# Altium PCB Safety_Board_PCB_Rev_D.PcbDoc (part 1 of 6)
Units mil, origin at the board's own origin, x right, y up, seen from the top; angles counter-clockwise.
Board outline 11000 x 4400 mil, 6 copper layers (L1-TOP, L2-Plane, L3-Signal, L4-Signal, L5-Plane, L6-BOT); 712 components, 540 nets, 2214 pads, 875 vias.
Unrouted connection lines stored in the file: 3.
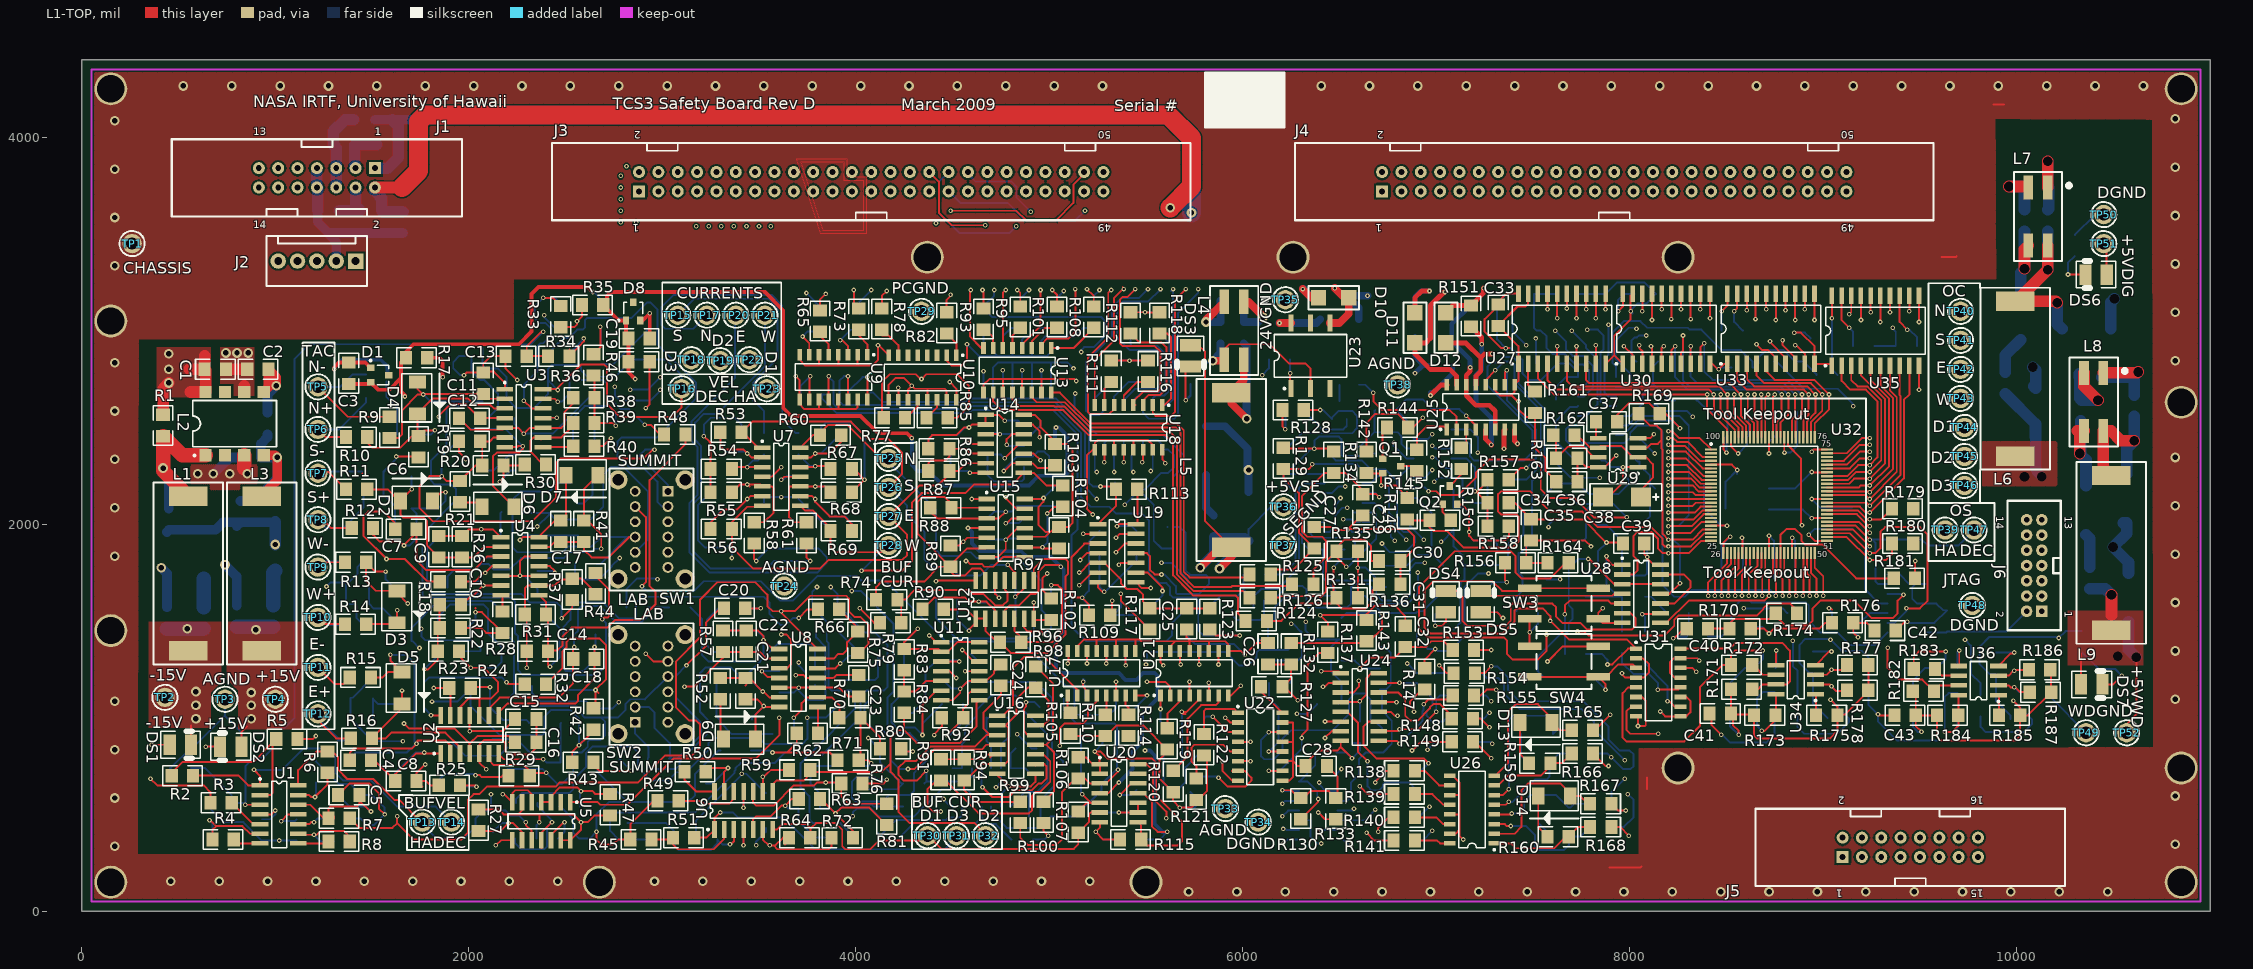
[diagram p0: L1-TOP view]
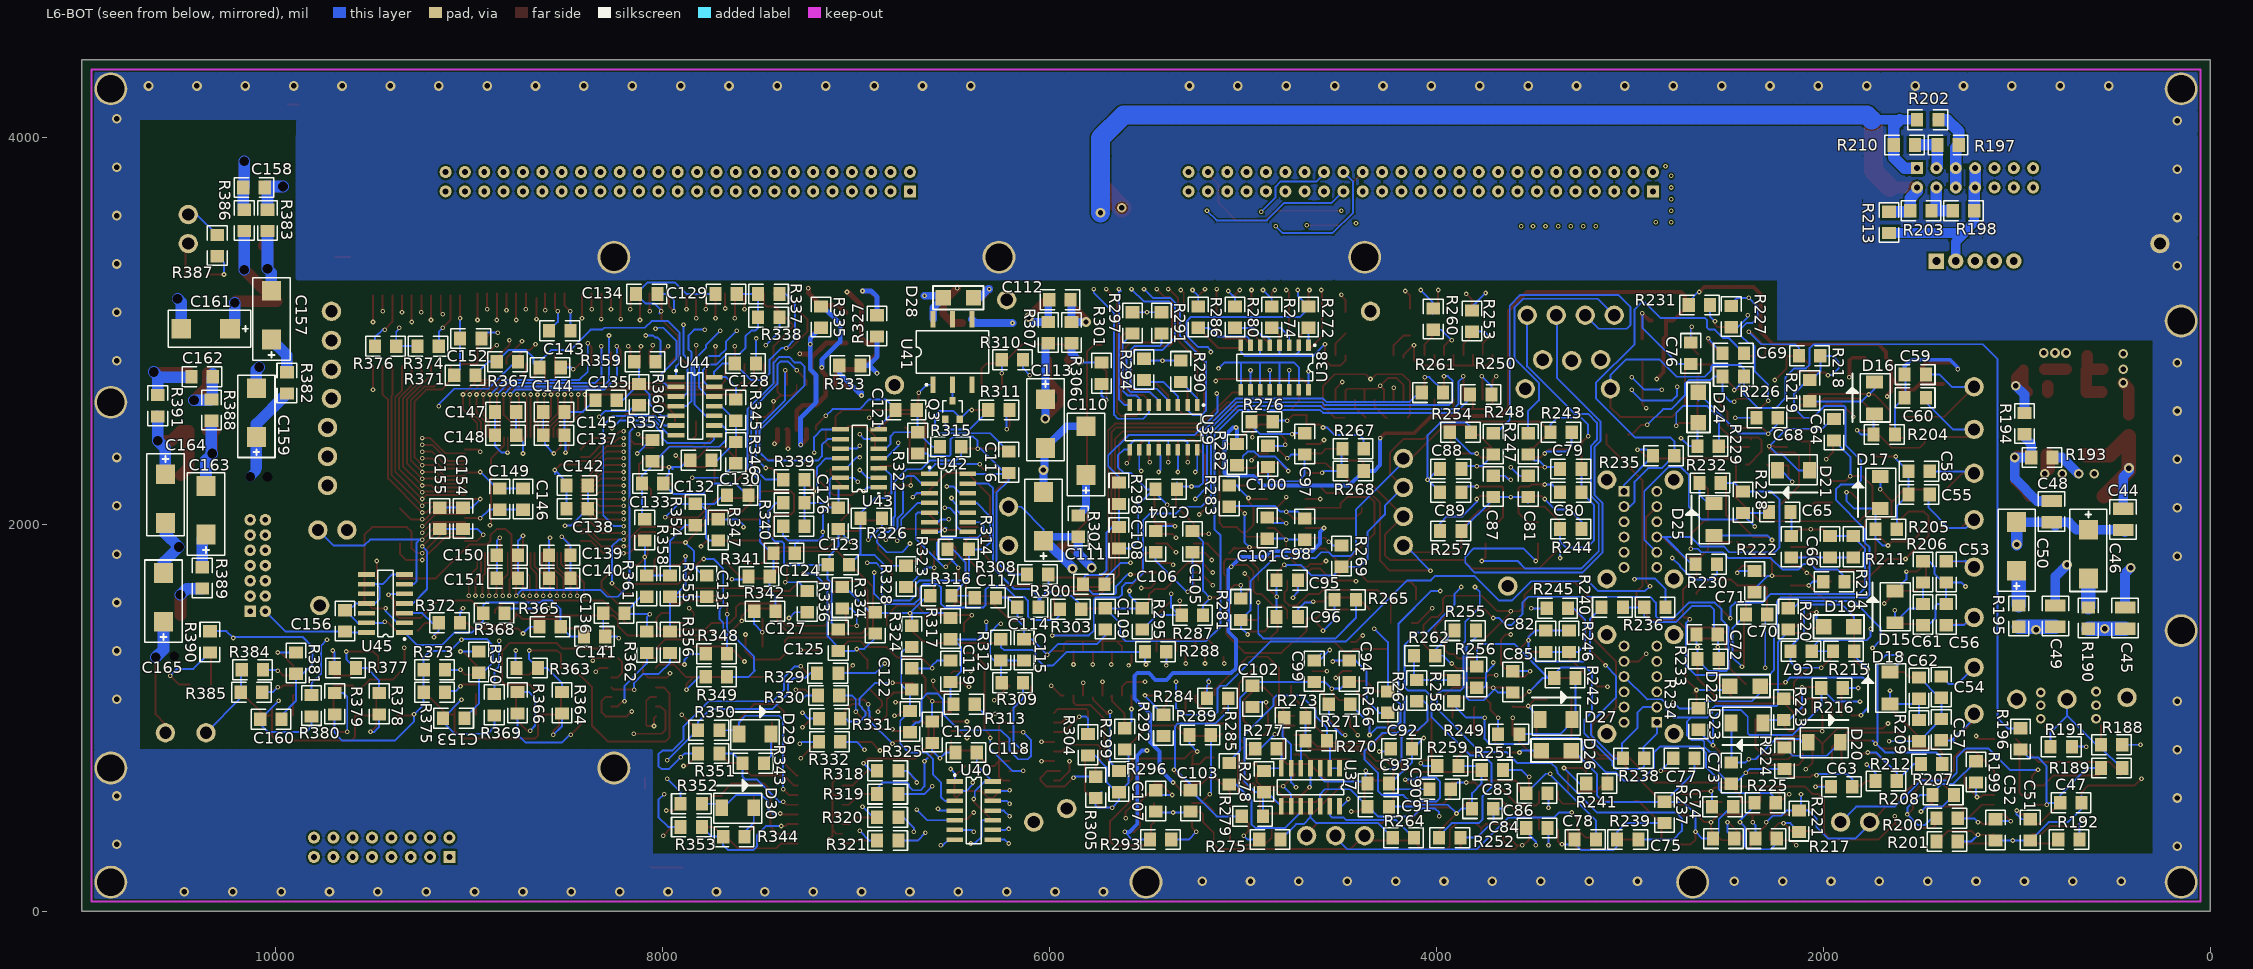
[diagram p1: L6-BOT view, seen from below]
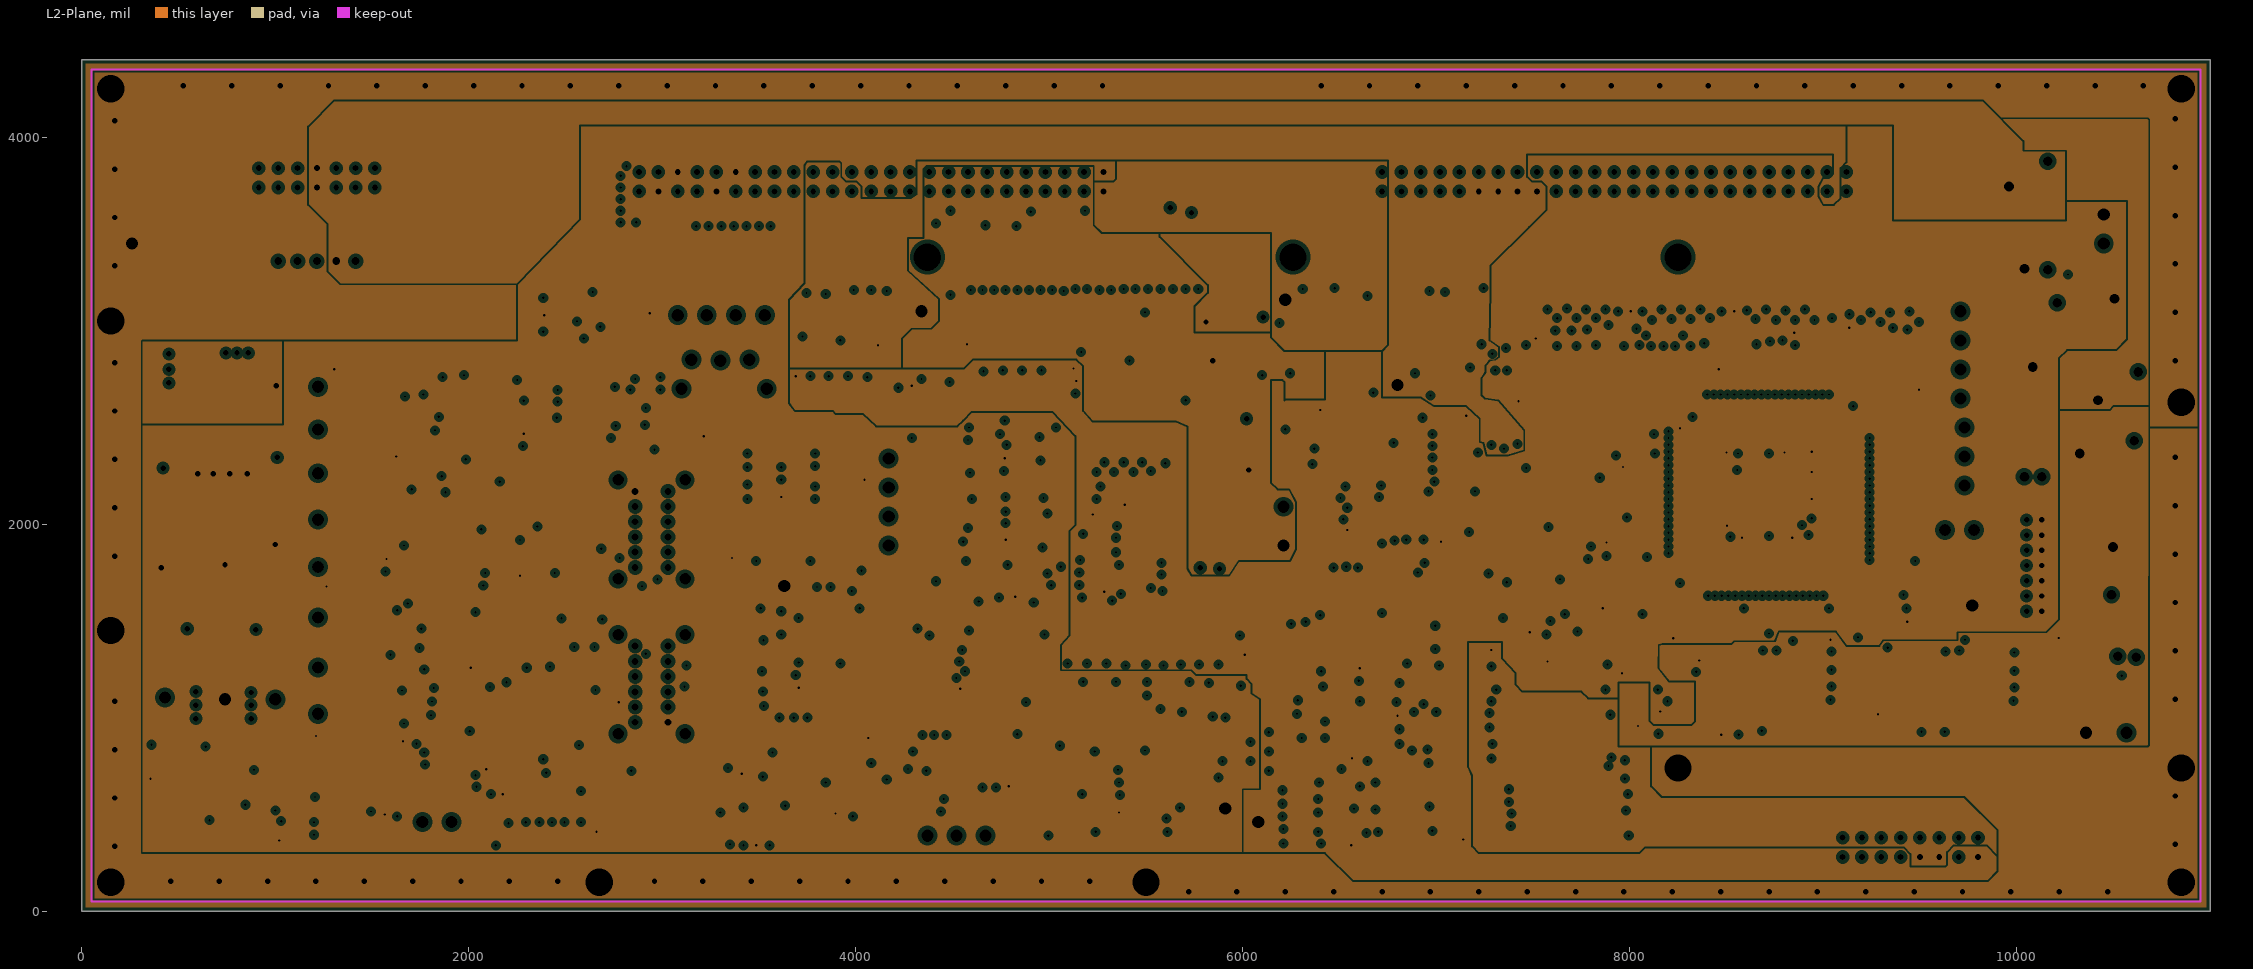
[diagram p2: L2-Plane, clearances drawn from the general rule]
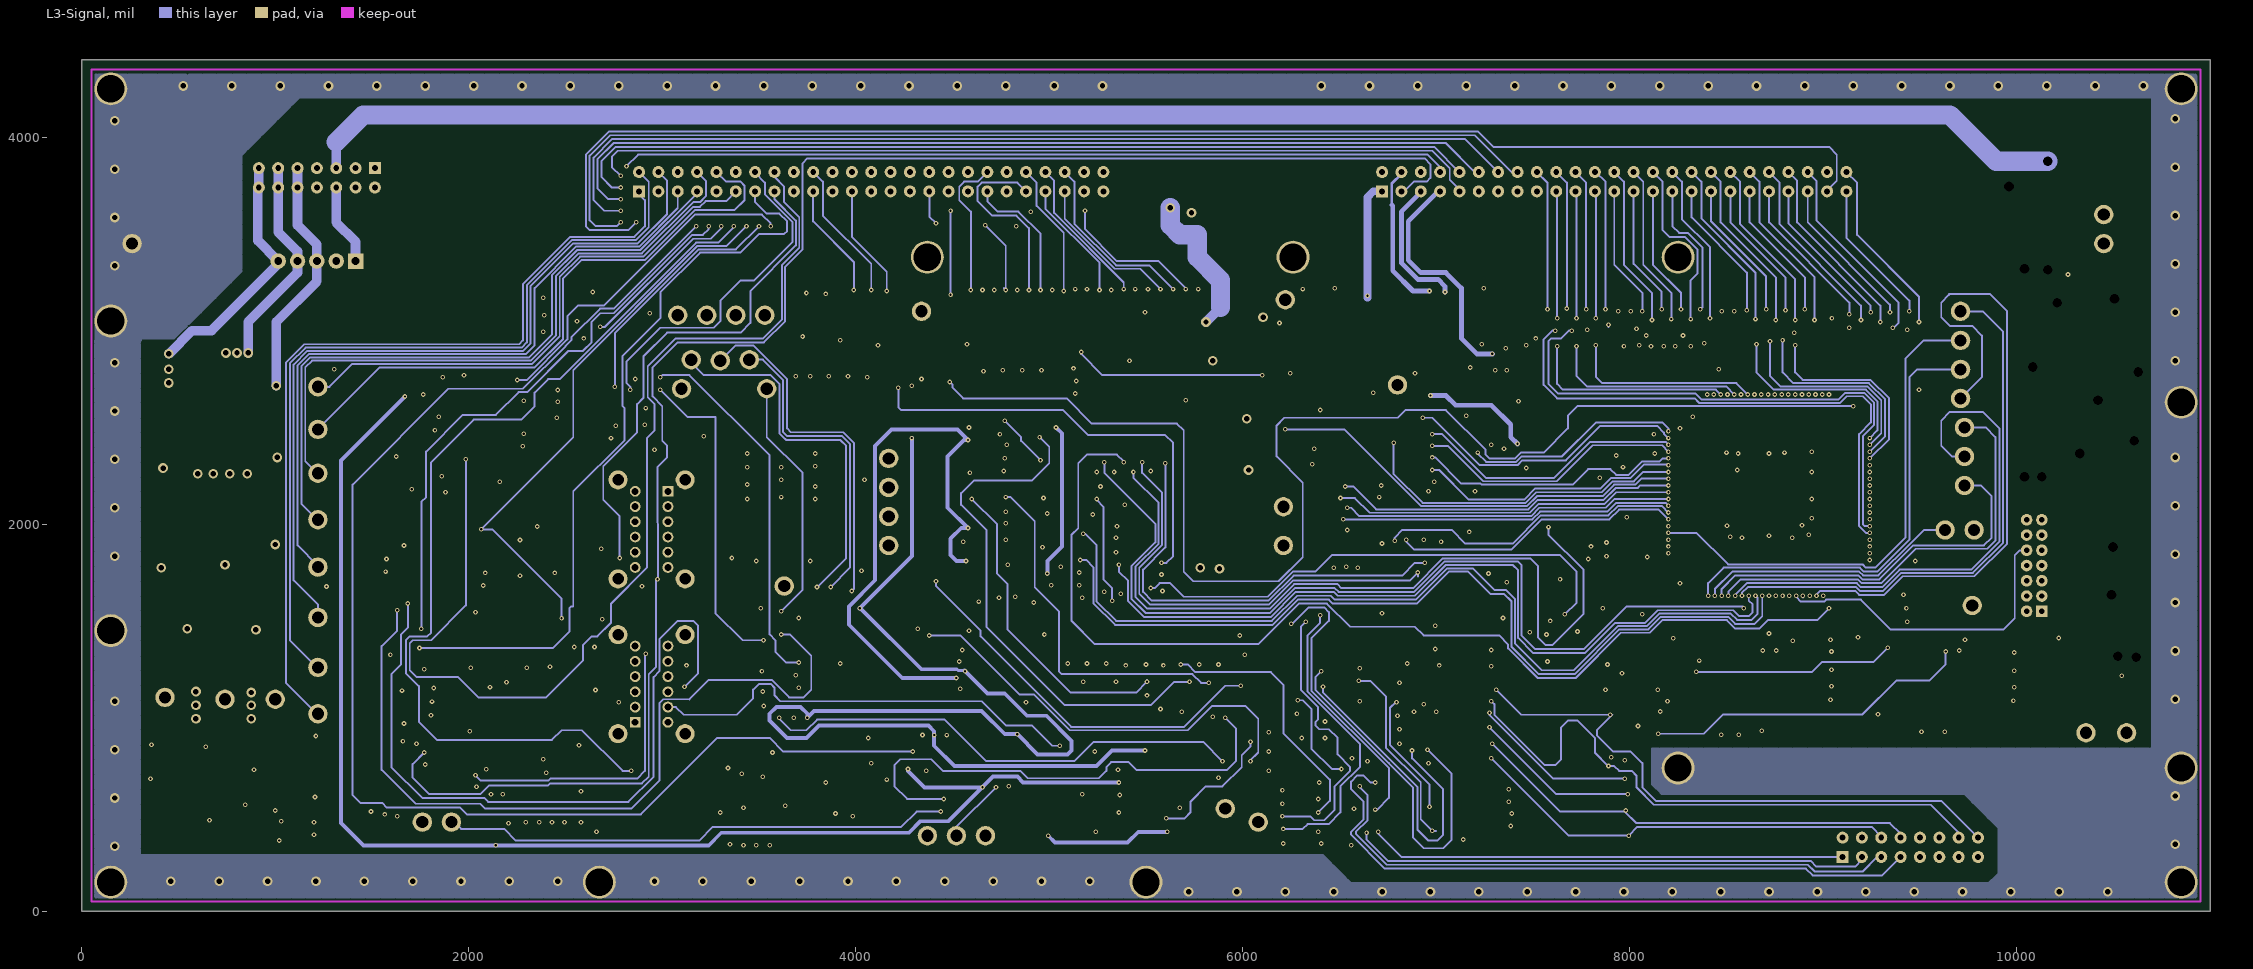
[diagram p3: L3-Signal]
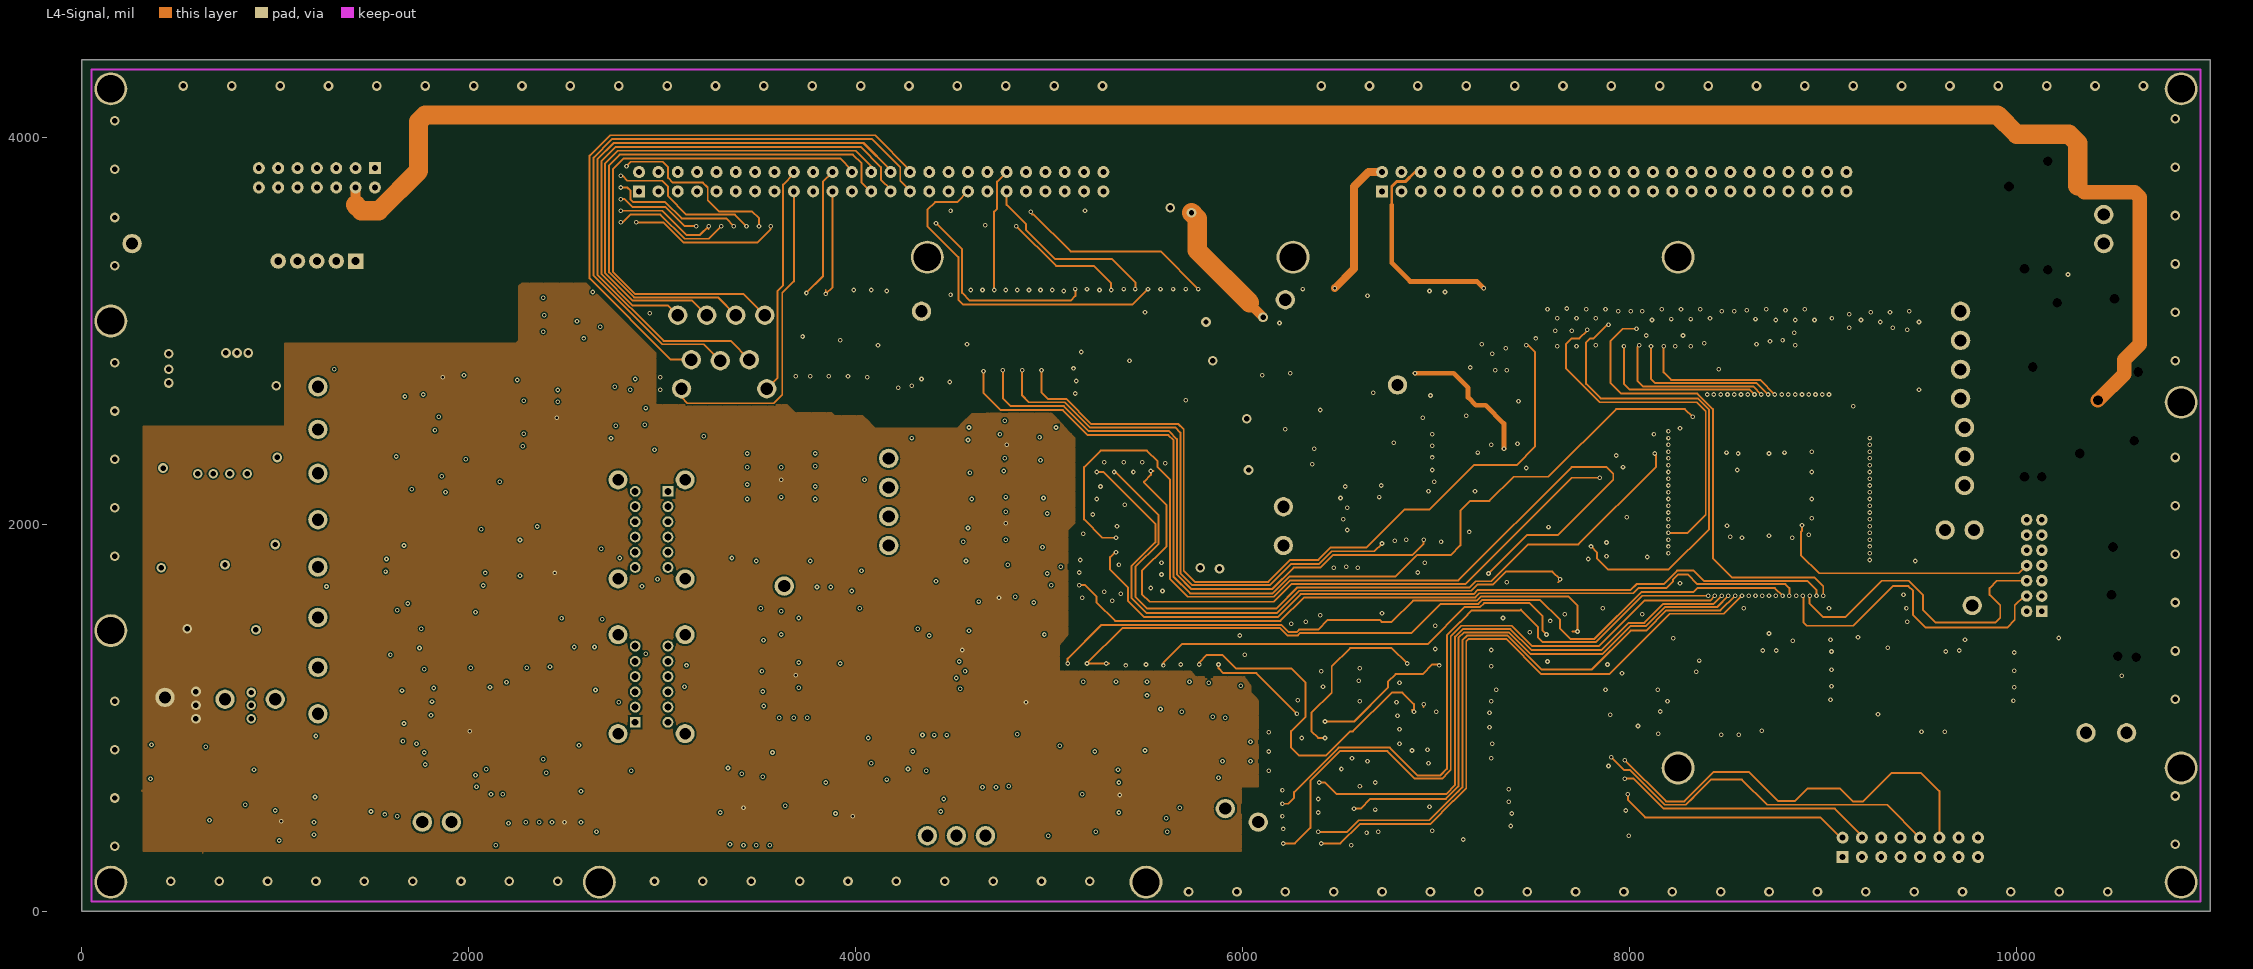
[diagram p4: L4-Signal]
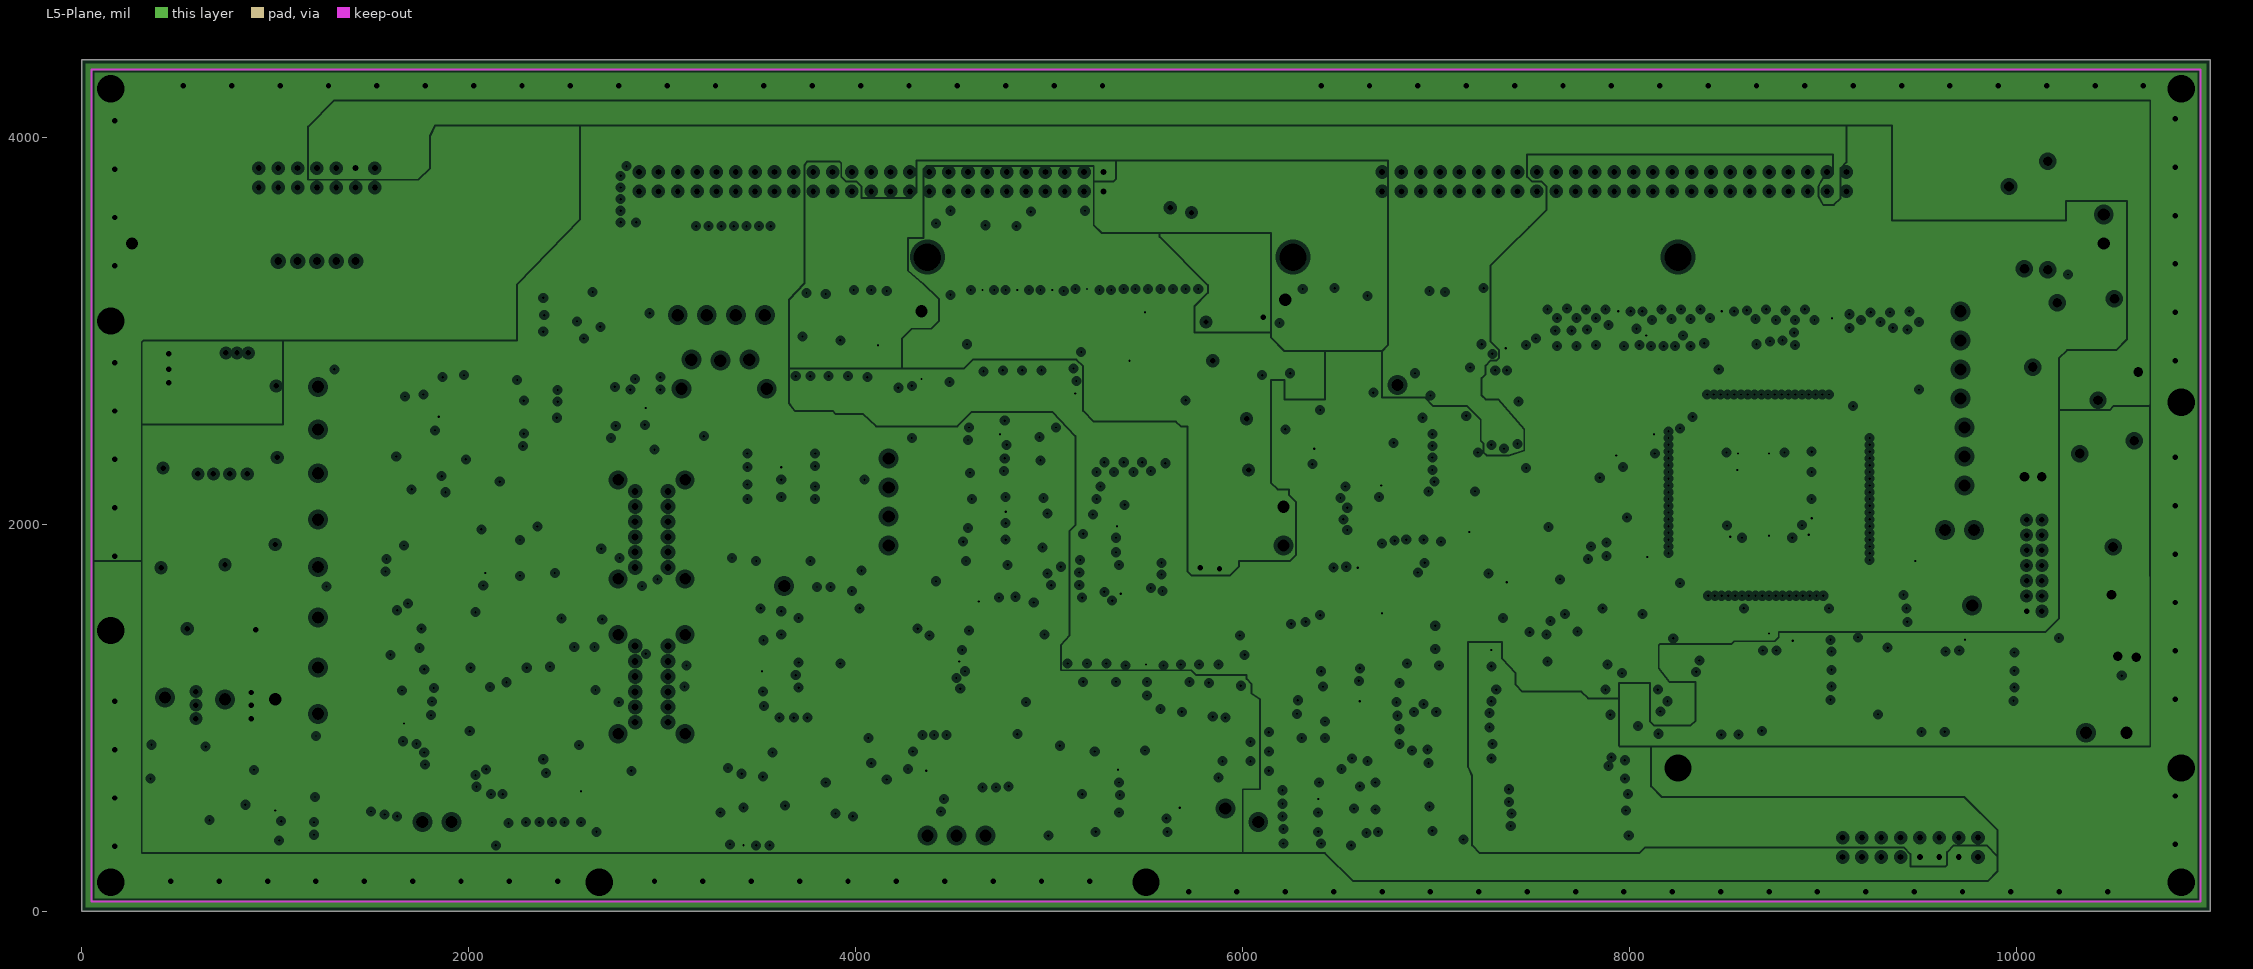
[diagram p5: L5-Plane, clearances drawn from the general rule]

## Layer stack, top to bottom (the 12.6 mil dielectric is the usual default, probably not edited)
L1-TOP: signal copper 1.4
Dielectric: core 12.6, FR-4, Dk 4.8
L2-Plane: plane copper 1.4, net (Multiple Nets)
Dielectric: prepreg 12.6, FR-4, Dk 4.8
L3-Signal: signal copper 1.4
Dielectric: core 12.6, FR-4, Dk 4.8
L4-Signal: signal copper 1.4
Dielectric: prepreg 12.6, FR-4, Dk 4.8
L5-Plane: plane copper 1.4, net (Multiple Nets)
Dielectric: core 12.6, FR-4, Dk 4.8
L6-BOT: signal copper 1.4

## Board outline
0,0 11000,0 11000,4400 0,4400 0,0

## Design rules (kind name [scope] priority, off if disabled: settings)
Clearance Clearance_1 [InPolygon vs IsPad] p1: gap=10
Clearance [All] p2: gap=7
ComponentClearance ComponentClearance_1 [All] p1: gap=2 collisioncheckmode=1
FanoutControl Fanout_BGA_1 [IsBGA] p1: bgadir=Out bgaviamode=Centered fanoutstyle=Auto fanoutdirection=Alternating viagrid=1 // Fanout_BGA (Default Rule)
FanoutControl Fanout_LCC_1 [IsLCC] p2: bgadir=Out bgaviamode=Centered fanoutstyle=Auto fanoutdirection=Alternating viagrid=1 // Fanout_LCC (Default Rule)
FanoutControl Fanout_SOIC_1 [IsSOIC] p3: bgadir=Out bgaviamode=Centered fanoutstyle=Auto fanoutdirection=Alternating viagrid=1 // Fanout_SOIC (Default Rule)
FanoutControl Fanout_Small_1 [(CompPinCount < 5)] p4: bgadir=Out bgaviamode=Centered fanoutstyle=Auto fanoutdirection=OutThenIn viagrid=1 // Fanout_Small (Default Rule)
FanoutControl Fanout_Default_1 [All] p5: bgadir=Out bgaviamode=Centered fanoutstyle=Auto fanoutdirection=Alternating viagrid=1 // Fanout_Default (Default Rule)
Height Height_1 [All] p1: minheight=0 maxheight=1000 prefheight=500
HoleSize HoleSize_1 [All] p1: absolutevalues=TRUE maxlimit=200 minlimit=1 maxpercent=80.000 minpercent=20.000
LayerPairs LayerPairs_1 [All] p1: enforce=TRUE
MatchedLengths "Encoder HA" [InNetClass('Encoder HA Nets')] p1: tolerance=100 amplitude=200 gap=20 style=90-Degree
MatchedLengths "Encoder DEC" [InNetClass('Encoder DEC Nets')] p2: tolerance=100 amplitude=200 gap=20 style=90-Degree
MatchedLengths JTAG [InNetClass('JTAG Nets')] p3: tolerance=50 amplitude=200 gap=20 style=90-Degree
PasteMaskExpansion PasteMaskExpansion_1 [All] p1: expansion=0
PlaneClearance PlaneClearance_1 [All] p1: clearance=20
PlaneConnect [All] p1: planeconnectstyle=Relief reliefexpansion=20 reliefentries=4 reliefconductorwidth=10 reliefairgap=10
PolygonConnect PolygonConnect_1 [All] p1: connectstyle=Direct reliefconductorwidth=10 reliefentries=4 polygonreliefangle="90 Angle"
RoutingLayers [All] p1: top layer=Horizontal mid layer 3="Not Used" mid layer 4="Not Used" bottom layer=Vertical
RoutingPriority RoutingPriority_1 [All] p1: routingpriority=0
RoutingTopology RoutingTopology_1 [All] p1: topology=Shortest
RoutingVias [All] p1: holewidth=28 width=50 viastyle="Through Hole" minholewidth=28 minwidth=50 maxholewidth=28 maxwidth=50
ShortCircuit ShortCircuit_1 [All] p1: allowed=FALSE
SolderMaskExpansion SolderMaskExpansion_1 [All] p1: expansion=4
TestPointUsage TestPointUsage_1 [All] p1: valid=0 allowmultiple=FALSE
Testpoint Testpoint_1 [All] p1: side=15 testpointundercomponent=TRUE minsize=40 maxsize=100 preferedsize=60 minholesize=0 maxholesize=40 preferedholesize=32 testpointgrid=1 style=1023 order=-539222988
UnRoutedNet UnRoutedNet_1 [All] p1:
Width [All] p1: maxlimit=250 minlimit=7 preferedwidth=10 toplayer_prefwidth=20 minimp=50.000000 maximp=50.000000 favimp=50.000000
1 further rules are at their usual default settings.

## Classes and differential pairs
component class Sheet_Symbol_WD: C39 C41 C43 C131 C136 C153 C160 DS4 DS5 R171 R172 R173 R175 R177 R178 R182 R183 R184 R185 R186 R187 R334 R336 R348 R349 R355 R356 R361 R362 R363 R364 R366 R369 R370 R373 R375 R377 R378 R379 R380 R381 R384 R385 SW3 SW4 U28 U31 U34 U36
component class Sheet_Symbol_Power_Filter: C1 C2 C3 C19 C44 C45 C46 C48 C49 C50 C110 C111 C112 C113 C157 C158 C159 C161 C162 C163 C164 C165 D1 D8 DS1 DS2 DS3 DS6 DS7 L1 L2 L3 L4 L5 L6 L7 L8 L9 R1 R17 R46 R188 R190 R191 R193 R194 R195 R197 R198 R202 R203 R210 R213 R301 R302 R306 R307 R382 R383 R386 R387 R388 R389 R390 R391 TP1 TP2 TP3 TP4 TP24 TP29 TP33 TP34 TP36 TP37 TP38 TP48 TP49 TP50 TP51 TP52
component class SB_PG1: J1 J2 J3 J4 J5
component class Sheet_Symbol_CPLD: C33 C36 C37 C38 C134 C137 C138 C139 C140 C142 C143 C145 C146 C147 C148 C149 C150 C151 C152 C154 C155 J6 R161 R162 R163 R169 R179 R180 R181 R374 R376 U27 U29 U30 U32 U33 U35
component class Sheet_Symbol_Dec_Tach: C6 C7 C9 C10 C11 C12 C13 C14 C17 C55 C58 C59 C60 C64 C65 C66 C67 C68 C69 C70 C71 C76 D2 D4 D6 D7 D16 D17 D19 D21 D24 D25 R9 R10 R11 R12 R18 R19 R20 R21 R22 R23 R26 R28 R30 R31 R33 R34 R35 R36 R37 R38 R39 R40 R41 R44 R48 R110 R204 R205 R211 R214 R215 R218 R219 R222 R226 R227 R228 R229 R230 R231 R232 R235 SW1 TP5 TP6 TP7 TP8 TP16 U3 U4
component class Sheet_Symbol_Encoder: C120 D13 D14 D29 D30 R138 R139 R140 R141 R148 R149 R153 R154 R155 R159 R160 R165 R166 R167 R168 R318 R319 R320 R321 R329 R330 R331 R332 R343 R344 R350 R351 R352 R353 U24 U26
component class Sheet_Symbol_HA_Tach: C4 C8 C15 C16 C18 C20 C21 C22 C23 C53 C54 C56 C57 C61 C62 C63 C72 C73 C77 C82 C85 C92 D3 D5 D9 D15 D18 D20 D22 D23 D26 D27 R13 R14 R15 R16 R24 R25 R29 R32 R42 R43 R52 R57 R62 R66 R70 R71 R75 R80 R206 R207 R209 R212 R216 R220 R223 R224 R233 R234 R236 R238 R240 R242 R245 R246 R249 R255 R256 R258 R259 R262 R263 R284 SW2 TP9 TP10 TP11 TP12 TP23 U2 U8
component class Sheet_Symbol_Input_Buffer: C25 C104 C105 C106 C108 C109 C121 C124 C128 C129 C135 C144 R65 R73 R78 R82 R109 R113 R117 R123 R250 R253 R260 R261 R272 R274 R280 R286 R287 R295 R298 R300 R315 R322 R323 R326 R337 R338 R359 R360 R367 R371 U9 U10 U19 U38 U44
component class Sheet_Symbol_Overcurrent: C35 C79 C81 C87 C88 C95 C96 C98 C101 C119 R53 R54 R60 R67 R74 R79 R88 R89 R90 R96 R102 R120 R156 R164 R243 R247 R248 R254 R265 R269 R281 R299 R313 R317 TP15 TP17 TP25 TP26 TP40 TP41 U7 U12 U15 U21
component class Sheet_Symbol_Overspeed: C5 C24 C32 C40 C47 C51 C52 C102 R2 R5 R6 R7 R27 R47 R91 R94 R98 R99 R100 R105 R137 R143 R170 R174 R189 R196 R199 R208 R217 R221 R225 R305 TP13 TP14 TP39 TP47 U1 U16 U17
component class Sheet_Symbol_Relays: C34 C126 D10 D11 D12 D28 Q1 Q2 Q3 R128 R142 R144 R145 R146 R150 R151 R152 R157 R158 R310 R311 R327 R333 R335 R339 R340 TP35 U23 U25 U41
component class Sheet_Symbol_Spares: C74 C75 R3 R4 R8 R49 R50 R77 R85 R114 R192 R200 R201 R241 R264 R275 R285 R288 R292 U5

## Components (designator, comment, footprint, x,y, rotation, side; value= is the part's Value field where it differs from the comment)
C1 "1uF" 1206 690,2800 r0 top
C2 "1uF" 1206 910,2800 r0 top
C3 "1uF" 1206 1380,2780 r270 top
C4 "0.022uF" 1206 1440,780 r180 top
C5 "1uF" 1206 1380,600 r0 top
C6 "0.022uF" 1206 1740,2400 r90 top
C7 "0.022uF" 1206 1674.65,1973.11 r0 top
C8 "0.068uF" 1206 1674.65,673.11 r0 top
C9 "0.022uF" 1206 1844.65,1883.11 r270 top
C10 "0.1uF" 1206 1904.65,1703.11 r0 top
C11 "0.022uF" 1206 2074.65,2728.11 r270 top
C12 "0.1uF" 1206 2004.65,2548.11 r0 top
C13 "0.068uF" 1206 2244.65,2868.11 r0 top
C14 "0.22uF" 1206 2354.65,1343.11 r0 top
C15 "0.1uF" 1206 2294.65,993.11 r180 top
C16 "0.1uF" 1206 2294.65,873.11 r180 top
C17 "2200pF" 1206 2474.65,1963.11 r90 top
C18 "1uF" 1206 2594.65,1303.11 r0 top
C19 "1uF" 1206 2880,2960 r180 top
C20 "0.33uF" 1206 3373.43,1565 r180 top
C21 "2200pF" 1206 3430,1150 r270 top
C22 "0.022uF" 1206 3433.43,1395 r270 top
C23 "0.1uF" 1206 4015,1165 r90 top
C24 "0.1uF" 1206 4750,1220 r270 top
C25 "1uF" 1206 5710,1510 r90 top
C26 "1uF" 1206 6130,1330 r270 top
C27 "1uF" 1206 6370,1930 r270 top
C28 "1uF" 1206 6380,750 r0 top
C29 "1uF" 1206 6620,2100 r90 top
C30 "1uF" 1206 6760,1810 r180 top
C31 "1uF" 1206 6760,1690 r180 top
C32 "1uF" 1206 6840,1420 r90 top
C33 "0.1uF" 1206 7320,3080 r90 top
C34 "1uF" 1206 7320,2110 r180 top
C35 "1uF" 1206 7490,1970 r270 top
C36 "0.1uF" 1206 7675,2220 r0 top
C37 "0.01uF" 1206 7880,2530 r180 top
C38 "10uF_25V" CAP_EIA_6032 7960,2140 r180 top
C39 "0.1uF" 1206 8020,1900 r0 top
C40 "1uF" 1206 8350,1460 r0 top
C41 "0.1uF" 1206 8467.97,1021.92 r0 top
C42 "1uF" 1206 9320,1450 r180 top
C43 "0.1uF" 1206 9422.96,1011.92 r0 top
C44 "22uF_15V" 1210 450,2025 r90 bottom
C45 "22uF_15V" 1210 440,1515 r270 bottom
C46 "100uF_25V" CAP_EIA_7343 630,1845 r270 bottom
C47 "1uF" 1206 720,560 r0 bottom
C48 "22uF_15V" 1210 820,2065 r90 bottom
C49 "22uF_15V" 1210 800,1525 r270 bottom
C50 "100uF_25V" CAP_EIA_7343 1000,1885 r90 bottom
C51 "0.1uF" 1206 930,420 r90 bottom
C52 "0.1uF" 1206 1110,420 r90 bottom
C53 "0.1uF" 1206 1364.65,1753.11 r90 bottom
C54 "0.1uF" 1206 1389.65,1158.11 r90 bottom
C55 "0.1uF" 1206 1504.65,2153.11 r180 bottom
C56 "0.1uF" 1206 1364.65,1533.11 r270 bottom
C57 "0.1uF" 1206 1389.65,938.11 r270 bottom
C58 "0.1uF" 1206 1504.65,2273.11 r180 bottom
C59 "0.1uF" 1206 1524.65,2773.11 r180 bottom
C60 "0.1uF" 1206 1524.65,2653.11 r180 bottom
C61 "0.022uF" 1206 1484.65,1533.11 r90 bottom
C62 "0.022uF" 1206 1504.65,1153.11 r270 bottom
C63 "0.33uF" 1206 1904.65,643.11 r180 bottom
C64 "2200pF" 1206 1944.65,2488.11 r90 bottom
C65 "0.33uF" 1206 2224.65,2063.11 r0 bottom
C66 "0.068uF" 1206 1964.65,1883.11 r270 bottom
C67 "0.1uF" 1206 2114.65,1343.11 r180 bottom
C68 "0.1uF" 1206 2290,2550 r0 bottom
C69 "0.33uF" 1206 2464.65,2883.11 r180 bottom
C70 "1uF" 1206 2344.65,1533.11 r0 bottom
C71 "0.1uF" 1206 2354.65,1703.11 r90 bottom
C72 "0.22uF" 1206 2600,1430 r0 bottom
C73 "2200pF" 1206 2474.65,713.11 r90 bottom
C74 "0.1uF" 1206 2520,540 r0 bottom
C75 "0.1uF" 1206 2515,375 r180 bottom
C76 "0.1uF" 1206 2684.65,2883.11 r90 bottom
C77 "0.1uF" 1206 2720,790 r0 bottom
C78 "1uF" 1206 3230,370 r0 bottom
C79 "1uF" 1206 3305,2285 r0 bottom
C80 "1uF" 1206 3305,2165 r0 bottom
C81 "0.1uF" 1206 3525,2195 r90 bottom
C82 "0.068uF" 1206 3433.43,1395 r270 bottom
C83 "0.1uF" 1206 3480,610 r180 bottom
C84 "0.1uF" 1206 3480,430 r180 bottom
C85 "0.1uF" 1206 3605,1185 r90 bottom
C86 "1uF" 1206 3760,530 r180 bottom
C87 "0.1uF" 1206 3705,2195 r90 bottom
C88 "1uF" 1206 3925,2285 r180 bottom
C89 "1uF" 1206 3925,2165 r180 bottom
C90 "1uF" 1206 3980,630 r180 bottom
C91 "0.1uF" 1206 4300,540 r0 bottom
C92 "0.1uF" 1206 4180,840 r0 bottom
C93 "0.1uF" 1206 4300,660 r0 bottom
C94 "0.1uF" 1206 4450,1240.12 r90 bottom
C95 "0.1uF" 1206 4770,1710 r180 bottom
C96 "0.1uF" 1206 4770,1520 r180 bottom
C97 "0.1uF" 1206 4680,2415 r90 bottom
C98 "0.1uF" 1206 4680,1975 r90 bottom
C99 "0.1uF" 1206 4630,1240.12 r90 bottom
C100 "0.1uF" 1206 4870,2350 r90 bottom
C101 "0.1uF" 1206 4873.43,1980 r90 bottom
C102 "0.1uF" 1206 4950,1110 r270 bottom
C103 "0.1uF" 1206 5270,570 r90 bottom
C104 "1uF" 1206 5395.12,2180 r180 bottom
C105 "1uF" 1206 5260,1910 r90 bottom
C106 "0.1uF" 1206 5450,1910 r90 bottom
C107 "0.1uF" 1206 5450,570 r90 bottom
C108 "1uF" 1206 5640,1930 r90 bottom
C109 "1uF" 1206 5710,1510 r90 bottom
C110 "470uF_10V" CAP_EIA_7343 5810,2380 r90 bottom
C111 "100uF_25V" CAP_EIA_7343 6030,2040 r90 bottom
C112 "1uF" 1206 5945,3160 r0 bottom
C113 "100uF_25V" CAP_EIA_7343 6020,2520 r270 bottom
C114 "1uF" 1206 6110,1570 r180 bottom
C115 "1uF" 1206 6130,1350 r270 bottom
C116 "0.1uF" 1206 6210,2320 r270 bottom
C117 "1uF" 1206 6330,1620 r0 bottom
C118 "0.1uF" 1206 6430,820 r180 bottom
C119 "1uF" 1206 6510,1240 r270 bottom
C120 "0.1uF" 1206 6605,925 r90 bottom
C121 "1uF" 1206 6740,2590 r180 bottom
C122 "1uF" 1206 6710,1200 r270 bottom
C123 "0.1uF" 1206 7090,2030 r90 bottom
C124 "1uF" 1206 7090,1790 r180 bottom
C125 "1uF" 1206 7090,1400 r270 bottom
C126 "1uF" 1206 7320,2110 r180 bottom
C127 "1uF" 1206 7470,1550 r180 bottom
C128 "0.1uF" 1206 7570,2830 r0 bottom
C129 "1uF" 1206 7670,3190 r180 bottom
C130 "1uF" 1206 7610,2150 r0 bottom
C131 "1uF" 1206 7770,1680 r270 bottom
C132 "1uF" 1206 7800,2330 r180 bottom
C133 "1uF" 1206 8050,2210 r0 bottom
C134 "0.1uF" 1206 8080,3190 r180 bottom
C135 "1uF" 1206 8290,2640 r180 bottom
C136 "1uF" 1206 8250,1540 r180 bottom
C137 "0.1uF" 1206 8560,2460 r0 bottom
C138 "1uF" 1206 8440,2080 r0 bottom
C139 "1uF" 1206 8530,1840 r180 bottom
C140 "0.1uF" 1206 8530,1720 r180 bottom
C141 "1uF" 1206 8350,1420 r0 bottom
C142 "0.1uF" 1206 8440,2200 r0 bottom
C143 "0.1uF" 1206 8530,3000 r180 bottom
C144 "1uF" 1206 8580,2810 r0 bottom
C145 "1uF" 1206 8560,2580 r0 bottom
C146 "0.1uF" 1206 8720,2130 r270 bottom
C147 "0.1uF" 1206 8810,2580 r180 bottom
C148 "1uF" 1206 8810,2460 r180 bottom
C149 "1uF" 1206 8840,2130 r270 bottom
C150 "1uF" 1206 8800,1840 r180 bottom
C151 "0.1uF" 1206 8800,1720 r180 bottom
C152 "0.1uF" 1206 8990,2960 r0 bottom
C153 "0.1uF" 1206 9077.96,996.92 r0 bottom
C154 "1uF" 1206 9030,2030 r270 bottom
C155 "0.1uF" 1206 9150,2030 r270 bottom
C156 "0.1uF" 1206 9640,1500 r270 bottom
C157 "470uF_10V" CAP_EIA_7343 10020,3080 r90 bottom
C158 "1uF" 1206 10110,3740 r0 bottom
C159 "100uF_25V" CAP_EIA_7343 10097.96,2576.92 r90 bottom
C160 "0.1uF" 1206 10022.96,991.92 r0 bottom
C161 "100uF_25V" CAP_EIA_7343 10360,3010 r0 bottom
C162 "1uF" 1206 10377.96,2761.92 r0 bottom
C163 "470uF_10V" CAP_EIA_7343 10357.96,2071.92 r90 bottom
C164 "100uF_25V" CAP_EIA_7343 10567.96,2131.92 r270 bottom
C165 "100uF_25V" CAP_EIA_7343 10577.96,1621.92 r90 bottom
D1 "LM4040DIM3-5.0/NOPB" SOT23 1540,2770 r270 top
D2 "RS1DB-13" "DO-214AA (SMB) & MARKING" 1730,2120 r0 top
D3 "RS1DB-13" "DO-214AA (SMB) & MARKING" 1629.65,1573.11 r270 top
D4 "RS1DB-13" "DO-214AA (SMB) & MARKING" 1734.65,2653.11 r270 top
D5 "RS1DB-13" "DO-214AA (SMB) & MARKING" 1654.65,1153.11 r270 top
D6 "RS1DB-13" "DO-214AA (SMB) & MARKING" 2150,2090 r0 top
D7 "RS1DB-13" "DO-214AA (SMB) & MARKING" 2584.65,2253.11 r180 top
D8 "LM4040DIM3-5.0/NOPB" SOT23 2850,3100 r0 top
D9 "RS1DB-13" "DO-214AA (SMB) & MARKING" 3400,890 r0 top
D10 "SMAJ26CA" "DO-214AC (SMA)" 6470,3170 r180 top
D11 "SMAJ26CA" "DO-214AC (SMA)" 6890,3015 r90 top
D12 "SMAJ26CA" "DO-214AC (SMA)" 7050,3015 r90 top
D13 "RS1DB-13" "DO-214AA (SMB) & MARKING" 7515,975 r180 top
D14 "RS1DB-13" "DO-214AA (SMB) & MARKING" 7610,595 r180 top
D15 "RS1DB-13" "DO-214AA (SMB) & MARKING" 1629.65,1573.11 r90 bottom
D16 "RS1DB-13" "DO-214AA (SMB) & MARKING" 1734.65,2653.11 r90 bottom
D17 "RS1DB-13" "DO-214AA (SMB) & MARKING" 1704.65,2163.11 r90 bottom
D18 "RS1DB-13" "DO-214AA (SMB) & MARKING" 1654.65,1153.11 r90 bottom
D19 "1SMA10CAT3G" "DO-214AC (SMA)" 1920,1470 r0 bottom
D20 "RS1DB-13" "DO-214AA (SMB) & MARKING" 1994.65,873.11 r180 bottom
D21 "RS1DB-13" "DO-214AA (SMB) & MARKING" 2154.65,2278.11 r0 bottom
D22 "1SMA10CAT3G" "DO-214AC (SMA)" 2404.65,1163.11 r0 bottom
D23 "RS1DB-13" "DO-214AA (SMB) & MARKING" 2394.65,973.11 r0 bottom
D24 "1SMA10CAT3G" "DO-214AC (SMA)" 2644.65,2603.11 r270 bottom
D25 "RS1DB-13" "DO-214AA (SMB) & MARKING" 2564.65,2023.11 r90 bottom
D26 "1SMA10CAT3G" "DO-214AC (SMA)" 3380,830 r0 bottom
D27 "RS1DB-13" "DO-214AA (SMB) & MARKING" 3380,990 r180 bottom
D28 "SMAJ26CA" "DO-214AC (SMA)" 6470,3170 r0 bottom
D29 "RS1DB-13" "DO-214AA (SMB) & MARKING" 7520,915 r180 bottom
D30 "RS1DB-13" "DO-214AA (SMB) & MARKING" 7610,535 r180 bottom
DS1 "LTST-C930KGKT" LED_1210 510,860 r0 top
DS2 "LTST-C930KGKT" LED_1210 770,850 r180 top
DS3 "LTST-C930KGKT" LED_1210 5730,2870 r270 top
DS4 "LTST-C930KGKT" LED_1210 7050,1600 r90 top
DS5 "LTST-C930KGKT" LED_1210 7230,1600 r90 top
DS6 "LTST-C930KGKT" LED_1210 10410,3290 r180 top
DS7 "LTST-C930KGKT" LED_1210 10387.97,1171.92 r0 top
J1 "Header_14_(7X2)_STR_SHD_LATCH_col1" 5499922-2 1515,3840 r270 top locked
J2 "*" 22-23-2051 1215,3360 r90 top
J3 "Header_50_(25X2)_STR_SHD_LATCH_col1" 1-5499923-0 2880,3720 r90 top locked
J4 "Header_50_(25X2)_STR_SHD_LATCH_col1" 1-5499923-0 6720,3720 r90 top locked
J5 "Header_16_(8X2)_STR_SHD_LATCH_col1" 5499922-3 9100,280 r90 top
J6 "Header_14_(7X2)_STR_SHD_col2" HDR_87831-1420 10130,1550 r180 top
L1 "8532-46LTR" 8532_inductor 550,1745 r270 top
L2 "ZJYS51R5-M4PAT-01" ZJYS51R5-M4PA_INDCUTOR 790,2520 r0 top
L3 "8532-46LTR" 8532_inductor 930,1745 r270 top
L4 "50105C" 5000_inductor 5955,3000 r270 top
L5 "8532-38LTR" 8532_inductor 5940,2280 r270 top
L6 "8532-38LTR" 8532_inductor 9992.96,2751.92 r270 top
L7 "50105C" 5000_inductor 10110,3590 r270 top
L8 "50105C" 5000_INDUCTOR 10397.96,2631.92 r270 top
L9 "8532-38LTR" 8532_inductor 10487.96,1851.92 r270 top
Q1 "MMBT3906" SOT23 6770,2300 r270 top
Q2 "MMBT3906" SOT23 7070,2150 r0 top
Q3 "MMBT3904" SOT23 6500,2590 r180 bottom
R1 "0_jumper" 1206 420,2510 r270 top
R2 "10000" 1206 520,700 r0 top
R3 "0_jumper" 1206 720,560 r0 top
R4 "0_jumper" 1206 730,370 r0 top
R5 "20000" 1206 1060,890 r180 top
R6 "10000" 1206 1270,770 r90 top
R7 "10000" 1206 1330,480 r180 top
R8 "0_jumper" 1206 1330,360 r180 top
R9 "47500" 1206 1590,2500 r270 top
R10 "47500" 1206 1420,2450 r0 top
R11 "47500" 1206 1420,2180 r0 top
R12 "47500" 1206 1450,1980 r0 top
R13 "47500" 1206 1414.65,1803.11 r0 top
R14 "47500" 1206 1414.65,1483.11 r0 top
R15 "47500" 1206 1439.65,1208.11 r0 top
R16 "47500" 1206 1444.65,893.11 r0 top
R17 "4870" 1206 1730,2860 r180 top
R18 "200000" 1206 1904.65,1583.11 r180 top
R19 "301000" 1206 2004.65,2428.11 r0 top
R20 "301000" 1206 2124.65,2303.11 r0 top
R21 "301000" 1206 1954.65,2168.11 r270 top
R22 "6810" 1206 1904.65,1463.11 r0 top
R23 "4870" 1206 1894.65,1343.11 r180 top
R24 "200000" 1206 1954.65,1153.11 r180 top
R25 "56200" 1206 1900,650 r0 top
R26 "10000" 1206 1964.65,1883.11 r270 top
R27 "100000" 1206 2050,470 r90 top
R28 "2000" 1206 2174.65,1493.11 r270 top
R29 "0_jumper" 1206 2260,700 r0 top
R30 "200000" 1206 2344.65,2308.11 r0 top
R31 "33200" 1206 2344.65,1533.11 r0 top
R32 "2000" 1206 2344.65,1173.11 r0 top
R33 "200000" 1206 2474.65,3073.11 r90 top
R34 "56200" 1206 2464.65,2868.11 r0 top
R35 "20000" 1206 2639.65,3133.11 r0 top
R36 "100" 1206 2644.65,2823.11 r90 top
R37 "68100" 1206 2534.65,1663.11 r90 top
R38 "4870" 1206 2594.65,2653.11 r0 top
R39 "200000" 1206 2594.65,2523.11 r0 top
R40 "2000" 1206 2594.65,2403.11 r0 top
R41 "301000" 1206 2594.65,1963.11 r90 top
R42 "6810" 1206 2644.65,993.11 r90 top
R43 "100" 1206 2590,770 r0 top
R44 "68100" 1206 2654.65,1693.11 r90 top
R45 "40200" 1206 2890,370 r0 top
R46 "4870" 1206 2880,2840 r0 top
R47 "10000" 1206 2730,550 r90 top
R48 "200000" 1206 3064.65,2463.11 r180 top
R49 "0_jumper" 1206 3030,570 r0 top
R50 "0_jumper" 1206 3170,720 r180 top
R51 "10000" 1206 3110,380 r0 top
R52 "301000" 1206 3300,1150 r270 top
R53 "10000" 1206 3355,2475 r0 top
R54 "0_jumper" 1206 3305,2285 r0 top
R55 "0_jumper" 1206 3305,2165 r0 top
R56 "10000" 1206 3305,1975 r0 top
R57 "10000" 1206 3313.43,1395 r90 top
R58 "10000" 1206 3475,1955 r90 top
R59 "10000" 1206 3710,730 r0 top
R60 "10000" 1206 3870,2460 r180 top
R61 "10000" 1206 3745,1955 r90 top
R62 "2000" 1206 3750,920 r180 top
R63 "0_jumper" 1206 3760,580 r180 top
R64 "10000" 1206 3710,380 r0 top
R65 "1000" 1206 3815,3050 r270 top
R66 "200000" 1206 3860,1560 r0 top
R67 "0_jumper" 1206 3925,2285 r180 top
R68 "0_jumper" 1206 3925,2165 r180 top
R69 "10000" 1206 3925,1965 r180 top
R70 "200000" 1206 3970,1000 r0 top
R71 "6810" 1206 3960,780 r180 top
R72 "40200" 1206 3930,380 r180 top
R73 "1000" 1206 4015,3060 r270 top
R74 "100000" 1206 4160,1610 r180 top
R75 "182000" 1206 4010,1390 r270 top
R76 "10000" 1206 3980,660 r180 top
R77 "10000" 1206 4200,2550 r180 top
R78 "1000" 1206 4135,3060 r270 top
R79 "1210" 1206 4180,1490 r0 top
R80 "100" 1206 4180,840 r0 top
R81 "0_jumper" 1206 4160,500 r90 top
R82 "2000" 1206 4470,3040 r90 top
R83 "100000" 1206 4250,1300.12 r90 top
R84 "1210" 1206 4250,1080.12 r90 top
R85 "10000" 1206 4420,2550 r0 top
R86 "100000" 1206 4430,2390 r180 top
R87 "1210" 1206 4430,2275 r180 top
R88 "10000" 1206 4440,2085 r180 top
R89 "100000" 1206 4490,1835 r270 top
R90 "10000" 1206 4400,1560 r180 top
R91 "1210" 1206 4440,730 r90 top
R92 "1210" 1206 4500,1000.12 r0 top
R93 "2000" 1206 4660,3060 r90 top
R94 "100000" 1206 4560,730 r270 top
R95 "2000" 1206 4850,3070 r90 top
R96 "100000" 1206 4800,1390 r180 top
R97 "100000" 1206 5050,1930 r90 top
R98 "100000" 1206 4930,1210 r270 top
R99 "10000" 1206 4850,510 r270 top
R100 "1210" 1206 4970,510 r90 top
R101 "2000" 1206 5040,3070 r90 top
R102 "1210" 1206 5010,1560 r270 top
R103 "100000" 1206 5030,2360 r90 top
R104 "1210" 1206 5070,2145 r270 top
R105 "4870" 1206 5110,970 r270 top
R106 "10000" 1206 5150,740 r270 top
R107 "1210" 1206 5150,460 r90 top
R108 "2000" 1206 5230,3070 r90 top
R109 "100" 1206 5260,1530 r0 top
R110 "4870" 1206 5290,960 r270 top
R111 "2000" 1206 5320,2790 r90 top
R112 "2000" 1206 5420,3040 r90 top
R113 "10000" 1206 5400,2180 r0 top
R114 "0_jumper" 1206 5410,960 r90 top
R115 "100000" 1206 5420,370 r0 top
R116 "2000" 1206 5510,2790 r90 top
R117 "10000" 1206 5520,1510 r270 top
R118 "2000" 1206 5570,3040 r90 top
R119 "4870" 1206 5610,890 r270 top
R120 "4870" 1206 5640.12,670.12 r270 top
R121 "4870" 1206 5760,630 r270 top
R122 "4870" 1206 5800,860 r270 top
R123 "100" 1206 5830,1510 r270 top
R124 "100" 1206 6070,1500 r180 top
R125 "100" 1206 6090,1740 r180 top
R126 "100" 1206 6090,1620 r180 top
R127 "100" 1206 6150,1160 r180 top
R128 "10000" 1206 6260,2590 r0 top
R129 "10000" 1206 6210,2340 r90 top
R130 "10000" 1206 6300,530 r270 top
R131 "100" 1206 6310,1690 r180 top
R132 "10000" 1206 6250,1330 r90 top
R133 "100" 1206 6480,530 r270 top
R134 "10000" 1206 6470,2320 r90 top
R135 "10000" 1206 6540,1860 r0 top
R136 "10000" 1206 6540,1620 r0 top
R137 "100" 1206 6440,1390 r270 top
R138 "0_jumper" 1206 6835,725 r0 top
R139 "0_jumper" 1206 6835,605 r0 top
R140 "0_jumper" 1206 6835,485 r0 top
R141 "0_jumper" 1206 6835,365 r0 top
R142 "10000" 1206 6640,2320 r90 top
R143 "10000" 1206 6640,1450 r270 top
R144 "4870" 1206 6800,2500 r0 top
R145 "249" 1206 6900,2330 r270 top
R146 "10000" 1206 6850,2080 r90 top
R147 "100" 1206 6940,1200 r270 top
R148 "0_jumper" 1206 7135,995 r180 top
R149 "0_jumper" 1206 7135,875 r180 top
R150 "4870" 1206 7020,2020 r180 top
R151 "0_jumper" 1206 7180,3075 r270 top
R152 "249" 1206 7130,2340 r270 top
R153 "0_jumper" 1206 7140,1350 r0 top
R154 "0_jumper" 1206 7145,1230 r180 top
R155 "0_jumper" 1206 7140,1115 r180 top
R156 "10000" 1206 7410,1800 r180 top
R157 "100" 1206 7320,2230 r180 top
R158 "10000" 1206 7320,1990 r0 top
R159 "0_jumper" 1206 7535,765 r0 top
R160 "0_jumper" 1206 7630,385 r0 top
R161 "0_jumper" 1206 7510,2630 r90 top
R162 "4750" 1206 7660,2460 r180 top
R163 "4750" 1206 7674.84,2340.04 r0 top
R164 "100" 1206 7630,1800 r0 top
R165 "205" 1206 7755,935 r180 top
R166 "205" 1206 7755,815 r180 top
R167 "205" 1206 7850,555 r180 top
R168 "205" 1206 7850,435 r180 top
R169 "100000" 1206 8100,2570 r180 top
R170 "10000" 1206 8570,1460 r0 top
R171 "10000" 1206 8577.96,1146.92 r180 top
R172 "0_jumper" 1206 8577.96,1271.92 r0 top
R173 "0_jumper" 1206 8697.96,1011.92 r180 top
R174 "100" 1206 8810,1540 r0 top
R175 "10000" 1206 9017.96,1011.92 r0 top
R176 "10000" 1206 9100,1490 r180 top
R177 "0_jumper" 1206 9177.96,1271.92 r0 top
R178 "0_jumper" 1206 9177.96,1141.92 r0 top
R179 "0_jumper" 1206 9410,2080 r0 top
R180 "0_jumper" 1206 9410,1900 r0 top
R181 "10000" 1206 9420,1720 r0 top
R182 "10000" 1206 9517.96,1136.92 r180 top
R183 "0_jumper" 1206 9522.96,1251.92 r0 top
R184 "0_jumper" 1206 9642.96,1011.92 r180 top
R185 "10000" 1206 9962.96,1011.92 r0 top
R186 "0_jumper" 1206 10117.96,1246.92 r0 top
R187 "0_jumper" 1206 10122.96,1131.92 r0 top
R188 "4870" 1206 510,860 r180 bottom
R189 "0_jumper" 1206 510,740 r0 bottom
R190 "15.8" 1206 630,1515 r270 bottom
R191 "4870" 1206 770,850 r180 bottom
R192 "0_jumper" 1206 730,370 r180 bottom
R193 "1000" 1206 870,2345 r0 bottom
R194 "0_jumper" 1206 960,2520 r270 bottom
R195 "15.8" 1206 990,1525 r270 bottom
R196 "10000" 1206 980,890 r270 bottom
R197 "0_jumper" 1206 1355,3960 r0 bottom
R198 "0_jumper" 1206 1275,3620 r0 bottom
R199 "20000" 1206 1210,720 r270 bottom
R200 "0_jumper" 1206 1360,480 r180 bottom
R201 "0_jumper" 1206 1360,360 r180 bottom
R202 "0_jumper" 1206 1460,4090 r180 bottom
R203 "0_jumper" 1206 1495,3620 r180 bottom
R204 "10000" 1206 1684.65,2463.11 r0 bottom
R205 "10000" 1206 1674.65,1973.11 r180 bottom
R206 "10000" 1206 1484.65,1753.11 r270 bottom
R207 "12700" 1206 1440,760 r180 bottom
R208 "0_jumper" 1206 1380,600 r180 bottom
R209 "10000" 1206 1504.65,933.11 r270 bottom
R210 "0_jumper" 1206 1580,3960 r180 bottom
R211 "68100" 1206 1844.65,1883.11 r270 bottom
R212 "68100" 1206 1674.65,673.11 r0 bottom
R213 "0_jumper" 1206 1660,3560 r270 bottom
R214 "200000" 1206 1944.65,1703.11 r0 bottom
R215 "100" 1206 1894.65,1343.11 r0 bottom
R216 "200000" 1206 1954.65,1153.11 r0 bottom
R217 "100000" 1206 2295,375 r0 bottom
R218 "68100" 1206 2070,2870 r0 bottom
R219 "10000" 1206 2070,2690 r270 bottom
R220 "301000" 1206 2180,1510 r90 bottom
R221 "1210" 1206 2125,465 r270 bottom
R222 "56200" 1206 2164.65,1883.11 r90 bottom
R223 "301000" 1206 2204.65,1043.11 r270 bottom
R224 "301000" 1206 2200,790 r90 bottom
R225 "1210" 1206 2300,560 r0 bottom
R226 "182000" 1206 2464.65,2763.11 r180 bottom
R227 "0_jumper" 1206 2474.65,3073.11 r90 bottom
R228 "0_jumper" 1206 2414.65,2113.11 r90 bottom
R229 "6810" 1206 2594.65,2403.11 r0 bottom
R230 "301000" 1206 2604.65,1793.11 r180 bottom
R231 "20000" 1206 2639.65,3133.11 r180 bottom
R232 "301000" 1206 2584.65,2213.11 r0 bottom
R233 "33200" 1206 2594.65,1303.11 r0 bottom
R234 "4870" 1206 2644.65,993.11 r270 bottom
R235 "0_jumper" 1206 2824.65,2353.11 r0 bottom
R236 "68100" 1206 2870,1570 r0 bottom
R237 "0_jumper" 1206 2820,510 r270 bottom
R238 "0_jumper" 1206 2980,790 r180 bottom
R239 "10000" 1206 3010,370 r0 bottom
R240 "68100" 1206 3090,1570 r0 bottom
R241 "0_jumper" 1206 3170,660 r0 bottom
R242 "301000" 1206 3335,1205 r180 bottom
R243 "15000" 1206 3355,2475 r180 bottom
R244 "15000" 1206 3305,1975 r180 bottom
R245 "56200" 1206 3373.43,1565 r0 bottom
R246 "68100" 1206 3313.43,1395 r270 bottom
R247 "10000" 1206 3525,2415 r270 bottom
R248 "10000" 1206 3705,2415 r270 bottom
R249 "200000" 1206 3625,915 r0 bottom
R250 "100" 1206 3770,2670 r180 bottom
R251 "40200" 1206 3710,730 r180 bottom
R252 "10000" 1206 3930,380 r180 bottom
R253 "1000" 1206 3815,3050 r270 bottom
R254 "15000" 1206 3875,2475 r0 bottom
R255 "0_jumper" 1206 3850,1450 r0 bottom
R256 "301000" 1206 3790,1210 r90 bottom
R257 "15000" 1206 3925,1965 r0 bottom
R258 "20000" 1206 3910,1140 r270 bottom
R259 "4870" 1206 3940,750 r0 bottom
R260 "1000" 1206 4015,3060 r270 bottom
R261 "100" 1206 4020,2680 r180 bottom
R262 "200000" 1206 4060,1320 r180 bottom
R263 "20000" 1206 4100,1140 r90 bottom
R264 "0_jumper" 1206 4170,380 r180 bottom
R265 "100000" 1206 4470,1610 r0 bottom
R266 "10000" 1206 4250,1080.12 r270 bottom
R267 "100000" 1206 4430,2390 r180 bottom
R268 "1210" 1206 4430,2275 r0 bottom
R269 "1210" 1206 4490,1835 r90 bottom
R270 "100000" 1206 4620,880 r180 bottom
R271 "100000" 1206 4500,1070 r180 bottom
R272 "2000" 1206 4660,3070 r90 bottom
R273 "1210" 1206 4730,1000 r180 bottom
R274 "2000" 1206 4850,3070 r90 bottom
R275 "0_jumper" 1206 4860,370 r180 bottom
R276 "10000" 1206 4900,2530 r0 bottom
R277 "1210" 1206 4880,840 r180 bottom
R278 "100000" 1206 4890,670 r270 bottom
R279 "10000" 1206 4950,490 r0 bottom
R280 "2000" 1206 5040,3070 r90 bottom
R281 "1210" 1206 5010,1560 r90 bottom
R282 "1210" 1206 5030,2360 r270 bottom
R283 "10000" 1206 5070,2145 r270 bottom
R284 "4870" 1206 5130,1100 r180 bottom
R285 "0_jumper" 1206 5070,710 r270 bottom
R286 "2000" 1206 5230,3070 r90 bottom
R287 "10000" 1206 5260,1530 r0 bottom
R288 "10000" 1206 5450,1340 r0 bottom
R289 "100000" 1206 5220,910 r0 bottom
R290 "2000" 1206 5320,2790 r90 bottom
R291 "2000" 1206 5420,3040 r90 bottom
R292 "0_jumper" 1206 5410,960 r90 bottom
R293 "1210" 1206 5425,370 r180 bottom
R294 "2000" 1206 5510,2800 r90 bottom
R295 "10000" 1206 5520,1510 r270 bottom
R296 "4870" 1206 5640,670 r270 bottom
R297 "2000" 1206 5570,3040 r90 bottom
R298 "10000" 1206 5640,2160 r90 bottom
R299 "4870" 1206 5610,890 r270 bottom
R300 "100" 1206 5770,1690 r180 bottom
R301 "1000" 1206 5730,2780 r270 bottom
R302 "3.01" 1206 5850,1990 r270 bottom
R303 "100" 1206 5890,1560 r0 bottom
R304 "4870" 1206 5800,860 r270 bottom
R305 "4870" 1206 5760,640 r270 bottom
R306 "0_jumper" 1206 5885,2990 r270 bottom
R307 "0_jumper" 1206 6005,2990 r270 bottom
R308 "10000" 1206 6060,1740 r0 bottom
R309 "100" 1206 6190,1180 r180 bottom
R310 "249" 1206 6190,2850 r180 bottom
R311 "4870" 1206 6260,2590 r180 bottom
R312 "10000" 1206 6250,1350 r90 bottom
R313 "100" 1206 6440,1070 r180 bottom
R314 "100" 1206 6470,1870 r0 bottom
R315 "100" 1206 6510,2400 r180 bottom
R316 "10000" 1206 6560,1630 r0 bottom
R317 "10000" 1206 6510,1460 r90 bottom
R318 "0_jumper" 1206 6835,725 r180 bottom
R319 "0_jumper" 1206 6835,605 r180 bottom
R320 "0_jumper" 1206 6835,485 r180 bottom
R321 "0_jumper" 1206 6835,365 r180 bottom
R322 "10000" 1206 6680,2420 r270 bottom
R323 "10000" 1206 6740,1730 r270 bottom
R324 "10000" 1206 6710,1420 r90 bottom
R325 "100" 1206 6720,980 r270 bottom
R326 "100" 1206 6920,2030 r180 bottom
R327 "0_jumper" 1206 6890,3025 r270 bottom
R328 "10000" 1206 6900,1490 r90 bottom
R329 "0_jumper" 1206 7145,1230 r180 bottom
R330 "0_jumper" 1206 7140,1115 r180 bottom
R331 "0_jumper" 1206 7135,995 r180 bottom
R332 "0_jumper" 1206 7135,875 r180 bottom
R333 "0_jumper" 1206 7030,2820 r0 bottom
R334 "1000" 1206 7070,1620 r90 bottom
R335 "0_jumper" 1206 7180,3070 r90 bottom
R336 "1000" 1206 7250,1600 r90 bottom
R337 "10000" 1206 7450,3190 r180 bottom
R338 "100" 1206 7450,3070 r180 bottom
R339 "100" 1206 7320,2230 r180 bottom
R340 "10000" 1206 7320,1990 r0 bottom
R341 "10000" 1206 7370,1850 r180 bottom
R342 "100" 1206 7500,1730 r0 bottom
R343 "0_jumper" 1206 7530,765 r0 bottom
R344 "0_jumper" 1206 7630,385 r0 bottom
R345 "10000" 1206 7620,2590 r90 bottom
R346 "100" 1206 7620,2370 r270 bottom
R347 "100" 1206 7710,1970 r90 bottom
R348 "2000" 1206 7720,1330 r0 bottom
R349 "2000" 1206 7720,1211.26 r0 bottom
R350 "205" 1206 7760,935 r180 bottom
R351 "205" 1206 7760,815 r180 bottom
R352 "205" 1206 7850,555 r180 bottom
R353 "205" 1206 7850,435 r180 bottom
R354 "10000" 1206 7830,2050 r270 bottom
R355 "10000" 1206 7960,1680 r90 bottom
R356 "100" 1206 7960,1390 r270 bottom
R357 "100" 1206 8050,2380 r90 bottom
R358 "10000" 1206 8090,1970 r270 bottom
R359 "10000" 1206 8090,2840 r180 bottom
R360 "100" 1206 8120,2670 r270 bottom
R361 "10000" 1206 8080,1680 r90 bottom
R362 "100" 1206 8080,1390 r270 bottom
R363 "0_jumper" 1206 8697.96,1256.92 r0 bottom
R364 "2000" 1206 8517.96,1076.92 r270 bottom
R365 "10000" 1206 8580,1470 r0 bottom
R366 "0_jumper" 1206 8747.96,1076.92 r90 bottom
R367 "100" 1206 8800,2840 r180 bottom
R368 "100" 1206 8870,1540 r180 bottom
R369 "0_jumper" 1206 8867.96,1066.92 r90 bottom
R370 "0_jumper" 1206 8947.96,1286.92 r90 bottom
R371 "10000" 1206 9020,2770 r0 bottom
R372 "100" 1206 9100,1490 r180 bottom
R373 "0_jumper" 1206 9177.96,1246.92 r180 bottom
R374 "0_jumper" 1206 9210,2920 r0 bottom
R375 "0_jumper" 1206 9177.96,1131.92 r180 bottom
R376 "0_jumper" 1206 9430,2920 r180 bottom
R377 "0_jumper" 1206 9637.96,1256.92 r0 bottom
R378 "2000" 1206 9462.96,1071.92 r270 bottom
R379 "0_jumper" 1206 9692.96,1071.92 r90 bottom
R380 "0_jumper" 1206 9812.96,1061.92 r90 bottom
R381 "0_jumper" 1206 9892.96,1281.92 r90 bottom
R382 "3.01" 1206 9940,2730 r270 bottom
R383 "0_jumper" 1206 10040,3570 r270 bottom
R384 "0_jumper" 1206 10117.96,1246.92 r180 bottom
R385 "0_jumper" 1206 10122.96,1131.92 r180 bottom
R386 "0_jumper" 1206 10160,3570 r270 bottom
R387 "1000" 1206 10300,3440 r270 bottom
R388 "0_jumper" 1206 10330,2590 r270 bottom
R389 "3.01" 1206 10377.96,1721.92 r270 bottom
R390 "1000" 1206 10337.96,1391.92 r270 bottom
R391 "0_jumper" 1206 10607.96,2611.92 r270 bottom
SW1 "MSS420004" MSS420004 2944.65,1973.11 r270 top
SW2 "MSS420004" MSS420004 2944.65,1173.11 r90 top
SW3 "TL6120AF300QG" SWITCH_TL6120AF300QG 7660,1590 r270 top
SW4 "TL6120AF300QG" SWITCH_TL6120AF300QG 7660,1290 r90 top
TP1 "TP_5006" TP_COMPACT 260,3450 r0 top
TP2 "TP_5005" TP_COMPACT 430,1105 r0 top
TP3 "TP_5006" TP_COMPACT 740,1095 r0 top
TP4 "TP_5005" TP_COMPACT 1000,1095 r0 top
TP5 "TP_5009" TP_COMPACT 1220,2710 r0 top
TP6 "TP_5008" TP_COMPACT 1220,2490 r0 top
TP7 "TP_5009" TP_COMPACT 1220,2263.11 r0 top
TP8 "TP_5008" TP_COMPACT 1220,2023.11 r0 top
TP9 "TP_5009" TP_COMPACT 1220,1778.11 r0 top
TP10 "TP_5008" TP_COMPACT 1220,1518.11 r0 top
TP11 "TP_5009" TP_COMPACT 1220,1260 r0 top
TP12 "TP_5008" TP_COMPACT 1220,1020 r0 top
TP13 "TP_5007" TP_COMPACT 1760,460 r90 top
TP14 "TP_5007" TP_COMPACT 1910,460 r90 top
TP15 "TP_5007" TP_COMPACT 3080,3080 r0 top
TP16 "TP_5007" TP_COMPACT 3100,2700 r0 top
TP17 "TP_5007" TP_COMPACT 3230,3080 r0 top
TP18 "TP_5007" TP_COMPACT 3150,2850 r0 top
TP19 "TP_5007" TP_COMPACT 3300,2845 r0 top
TP20 "TP_5007" TP_COMPACT 3380,3080 r0 top
TP21 "TP_5007" TP_COMPACT 3530,3080 r0 top
TP22 "TP_5007" TP_COMPACT 3450,2850 r0 top
TP23 "TP_5007" TP_COMPACT 3540,2700 r0 top
TP24 "TP_5006" TP_COMPACT 3630,1680 r0 top
TP25 "TP_5007" TP_COMPACT 4170,2340 r0 top
TP26 "TP_5007" TP_COMPACT 4170,2190 r0 top
TP27 "TP_5007" TP_COMPACT 4170,2040 r0 top
TP28 "TP_5007" TP_COMPACT 4170,1890 r0 top
TP29 "TP_5006" TP_COMPACT 4340,3100 r0 top
TP30 "TP_5007" TP_COMPACT 4370,390 r0 top
TP31 "TP_5007" TP_COMPACT 4520,390 r0 top
TP32 "TP_5007" TP_COMPACT 4670,390 r0 top
TP33 "TP_5006" TP_COMPACT 5910,530 r0 top
TP34 "TP_5006" TP_COMPACT 6080,460 r0 top
TP35 "TP_5006" TP_COMPACT 6220,3160 r0 top
TP36 "TP_5005" TP_COMPACT 6210,2090 r90 top
TP37 "TP_5006" TP_COMPACT 6210,1890 r0 top
TP38 "TP_5006" TP_COMPACT 6800,2720 r180 top
TP39 "TP_5007" TP_COMPACT 9630,1970 r0 top
TP40 "TP_5007" TP_COMPACT 9710,3100 r0 top
TP41 "TP_5007" TP_COMPACT 9710,2950 r0 top
TP42 "TP_5007" TP_COMPACT 9710,2800 r0 top
TP43 "TP_5007" TP_COMPACT 9710,2650 r0 top
TP44 "TP_5007" TP_COMPACT 9730,2500 r0 top
TP45 "TP_5007" TP_COMPACT 9730,2350 r0 top
TP46 "TP_5007" TP_COMPACT 9730,2200 r0 top
TP47 "TP_5007" TP_COMPACT 9780,1970 r0 top
TP48 "TP_5006" TP_COMPACT 9770,1580 r0 top
TP49 "TP_5006" TP_COMPACT 10357.97,921.92 r0 top
TP50 "TP_5006" TP_COMPACT 10450,3600 r0 top
TP51 "TP_5005" TP_COMPACT 10450,3450 r90 top
TP52 "TP_5005" TP_COMPACT 10567.97,921.92 r0 top
U1 "OPA4277UA" SOIC_14_Narrow 1020,500 r270 top
U2 "OPA4277UA" SOIC_14_Narrow 2004.65,913.11 r0 top
U3 "OPA4277UA" SOIC_14_Narrow 2284.65,2548.11 r270 top
U4 "OPA4277UA" SOIC_14_Narrow 2264.65,1783.11 r270 top
U5 "LM339DR2G" SOIC_14_Narrow 2375,465 r180 top
U6 "OPA4277UA" SOIC_14_Narrow 3420,520 r0 top
U7 "OPA4277UA" SOIC_14_Narrow 3615,2245 r270 top
U8 "OPA4277UA" SOIC_14_Narrow 3703.43,1205 r270 top
U9 "TLP281-4" SOIC_16_C5.85 3885,2760 r180 top
U10 "TLP281-4" SOIC_16_C5.85 4345,2758 r180 top
U11 "LM339DR2G" SOIC_14_Narrow 4540,1240.12 r270 top
U12 "LM339DR2G" SOIC_14_Narrow 4770,1610 r0 top
U13 "TLP281-4" SOIC_16_C5.85 4835,2795 r180 top
U14 "LM339DR2G" SOIC_14_Narrow 4770,2415 r270 top
U15 "LM339DR2G" SOIC_14_Narrow 4775,1980 r270 top
U16 "LM339DR2G" SOIC_14_Narrow 4830,860 r270 top
U17 "TLP281-4" SOIC_16_C5.85 5270,1230 r0 top
U18 "TLP281-4" SOIC_16_C5.85 5410,2500 r180 top
U19 "M74HC14RM13TR" SOIC_14_Narrow 5350,1850 r270 top
U20 "LM339DR2G" SOIC_14_Narrow 5360,610 r270 top
U21 "TLP281-4" SOIC_16_C5.85 5750,1230 r0 top
U22 "TLP281-4" SOIC_16_C5.85 6090,850 r270 top
U23 "PS710EL-1A-A" SO_6_254P 6400,2870 r0 top
U24 "DS26LS32ACM" SOIC_16_NARROW 6605,1055 r270 top
U25 "TLP281-4" SOIC_16_C5.85 7230,2605 r0 top
U26 "TLP281-4" SOIC_16_C5.85 7185,525 r90 top
U27 "M74HCT541M1R" SOIC_20_WIDE 7650,3010 r0 top
U28 "M74HC14RM13TR" SOIC_14_Narrow 8060,1640 r270 top
U29 "TS555IDT" SOIC_8_NARROW 7939.96,2370.04 r90 top
U30 "M74HCT541M1R" SOIC_20_WIDE 8190,3010 r0 top
U31 "TLP281-4" SOIC_16_C5.85 8147.96,1181.92 r270 top
U32 "XC9572-15TQ100C" TQ100 8720,2150 r0 top locked
U33 "M74HCT541M1R" SOIC_20_WIDE 8730,3010 r0 top
U34 "MAX1232ESA+" SOIC_8_NARROW 8857.96,1196.92 r90 top
U35 "M74HCT541M1R" SOIC_20_WIDE 9270,3000 r0 top
U36 "MAX1232ESA+" SOIC_8_NARROW 9802.96,1191.92 r90 top
U37 "LM339DR2G" SOIC_14_Narrow 4650,640 r0 bottom
U38 "TLP281-4" SOIC_16_C5.85 4835,2810 r0 bottom
U39 "TLP281-4" SOIC_16_C5.85 5410,2500 r0 bottom
U40 "M74HC14RM13TR" SOIC_14_Narrow 6390,520 r270 bottom
U41 "PS710EL-1A-A" SO_6_254P 6450,2890 r180 bottom
U42 "M74HC14RM13TR" SOIC_14_Narrow 6520,2110 r270 bottom
U43 "M74HC14RM13TR" SOIC_14_Narrow 6980,2340 r90 bottom
U44 "M74HC14RM13TR" SOIC_14_Narrow 7830,2610 r270 bottom
U45 "M74HC14RM13TR" SOIC_14_Narrow 9430,1590 r90 bottom

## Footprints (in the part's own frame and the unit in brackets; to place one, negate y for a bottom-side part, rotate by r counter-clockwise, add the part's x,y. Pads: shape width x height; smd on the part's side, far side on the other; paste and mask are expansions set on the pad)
1-5499923-0 [mil] "Header, 50 pin, male, 2x25, shrouded, latch, vertical"
  rect 62x62 hole 30: 1(0,0)
  round 62 hole 30: 2(100,0) 3(0,-100) 4(100,-100) 5(0,-200) 6(100,-200) 7(0,-300) 8(100,-300) 9(0,-400) 10(100,-400) 11(0,-500) 12(100,-500) 13(0,-600) 14(100,-600) 15(0,-700) 16(100,-700) 17(0,-800) 18(100,-800) 19(0,-900) 20(100,-900) 21(0,-1000) 22(100,-1000) 23(0,-1100) 24(100,-1100) 25(0,-1200) 26(100,-1200) 27(0,-1300) 28(100,-1300) 29(0,-1400) 30(100,-1400) 31(0,-1500) 32(100,-1500) 33(0,-1600) 34(100,-1600) 35(0,-1700) 36(100,-1700) 37(0,-1800) 38(100,-1800) 39(0,-1900) 40(100,-1900) 41(0,-2000) 42(100,-2000) 43(0,-2100) 44(100,-2100) 45(0,-2200) 46(100,-2200) 47(0,-2300) 48(100,-2300) 49(0,-2400) 50(100,-2400)
  silkscreen extent -150,-2850 250,450
22-23-2051 [mil] "Header, 5 pin male, vertical (IRTF power connector)"
  rect 80x80 hole 40: 1(0,-200)
  round 80 hole 40: 2(0,-100) 3(0,0) 4(0,100) 5(0,200)
  silkscreen extent -130,-260 130,260
1206 [mm]
  rect 1.6x1.8 smd: 1(-1.4,0) 2(1.4,0)
  silkscreen extent -2.6,-1.3 2.6,1.3
1210 [mm]
  rect 1.6x2.7 smd: 1(-1.4,0) 2(1.4,0)
  silkscreen extent -2.6,-1.75 2.6,1.75
5000_inductor [mil] "Inductor, Common Mode"
  rect 125x50 smd: 1(-150,50) 2(-150,-50) 3(150,-50) 4(150,50)
  silkscreen extent -230,-125 230,170
5000_INDUCTOR [mil] "Inductor, Common Mode"
  rect 125x50 smd: 1(-150,50) 2(-150,-50) 3(150,-50) 4(150,50)
  silkscreen extent -230,-125 230,170
8532_inductor [mil] "Inductor, 8532 series"
  rect 100x200 smd: 1(-400,0) 2(400,0)
  silkscreen extent -470,-180 470,180
5499922-2 [mil] "Header, 14 pin, male, 2x7, shrouded, latch, vertical"
  rect 62x62 hole 30: 1(0,0)
  round 62 hole 30: 2(100,0) 3(0,-100) 4(100,-100) 5(0,-200) 6(100,-200) 7(0,-300) 8(100,-300) 9(0,-400) 10(100,-400) 11(0,-500) 12(100,-500) 13(0,-600) 14(100,-600)
  silkscreen extent -150,-1050 250,450
5499922-3 [mil] "Header, 16 pin, male, 2x8, shrouded, latch, vertical"
  rect 62x62 hole 30: 1(0,0)
  round 62 hole 30: 2(100,0) 3(0,-100) 4(100,-100) 5(0,-200) 6(100,-200) 7(0,-300) 8(100,-300) 9(0,-400) 10(100,-400) 11(0,-500) 12(100,-500) 13(0,-600) 14(100,-600) 15(0,-700) 16(100,-700)
  silkscreen extent -150,-1150 250,450
CAP_EIA_6032 [mm]
  rect 2.6x2.5 smd: 1(-2.5,0) 2(2.5,0)
  silkscreen extent -5.2,-1.78 4.2,1.78
CAP_EIA_7343 [mm]
  rect 2.6x2.5 smd: 1(-3.2,0) 2(3.2,0)
  silkscreen extent -5.9,-2.45 4.9,2.45
"DO-214AA (SMB) & MARKING" [mm]
  rect 1.7x2.2 smd: A(-2.1,0) K(2.1,0)
  silkscreen extent -3.17,-2.03 3.17,3.68
"DO-214AC (SMA)" [mil] "SMA"
  rect 80x80 smd: A(-78.5,0) K(78.5,0)
  silkscreen extent -130,-60 130,60
HDR_87831-1420 [mil] "Header, 7x2, straight, shroud, common use for JTAG"
  rect 60x60 hole 28: 1(0,0)
  round 60 hole 28: 2(78.74,0) 3(0,-78.74) 5(0,-157.48) 6(78.74,-157.48) 7(0,-236.22) 8(78.74,-236.22) 9(0,-314.96) 10(78.74,-314.96) 11(0,-393.7) 12(78.74,-393.7) 13(0,-472.44) 14(78.74,-472.44)
  round 59.06 hole 28: 4(78.74,-78.74)
  silkscreen extent -98,-571 177,98
LED_1210 [mm] "LED, 1210 case"
  rect 1.6x2.7 smd: A(-1.4,0) K(1.4,0)
  silkscreen extent -2.6,-1.78 2.6,1.78
MSS420004 [mm] "Switch, Slide, 4PDT"
  rect 1.422x1.422 hole 0.914: 1(-5,2.15)
  round 1.422 hole 0.914: 2(-3,2.15) 3(-1,2.15) 4(1,2.15) 5(3,2.15) 6(5,2.15) 7(-5,-2.15) 8(-3,-2.15) 9(-1,-2.15) 10(1,-2.15) 11(3,-2.15) 12(5,-2.15)
  round 2.5 hole 1.5: ""(-6.5,4.4) ""(-6.5,-4.4) ""(6.5,4.4) ""(6.5,-4.4)
  silkscreen extent -8,-5.5 8,5.5
SO_6_254P [mm] "Surface mount, 6 pin, 2.54mm spacing"
  rect 0.65x2.2 smd: 1(-3.81,-4.3) 2(-1.27,-4.3) 3(1.27,-4.3) 4(1.27,4.3) 5(-1.27,4.3) 6(-3.81,4.3)
  silkscreen extent -6,-4.42 3.5,2.8
SOIC_8_NARROW [mm] "8 pin Narrow SOIC"
  rect 0.6x2.2 smd: 1(-1.905,-2.6) 2(-0.635,-2.6) 3(0.635,-2.6) 4(1.905,-2.6) 5(1.905,2.6) 6(0.635,2.6) 7(-0.635,2.6) 8(-1.905,2.6)
  silkscreen extent -2.88,-2.72 2.5,1.1
SOIC_14_Narrow [mm] "14 pin Narrow SOIC"
  rect 0.6x2.2 smd: 1(-3.81,-2.5) 2(-2.54,-2.5) 3(-1.27,-2.5) 4(0,-2.5) 5(1.27,-2.5) 6(2.54,-2.5) 7(3.81,-2.5) 8(3.81,2.5) 9(2.54,2.5) 10(1.27,2.5) 11(0,2.5) 12(-1.27,2.5) 13(-2.54,2.5) 14(-3.81,2.5)
  silkscreen extent -4.78,-2.62 4.38,1
SOIC_16_C5.85 [mm]
  rect 0.6x1.55 smd: 1(-4.445,-2.925) 2(-3.175,-2.925) 3(-1.905,-2.925) 4(-0.635,-2.925) 5(0.635,-2.925) 6(1.905,-2.925) 7(3.175,-2.925) 8(4.445,-2.925) 9(4.445,2.925) 10(3.175,2.925) 11(1.905,2.925) 12(0.635,2.925) 13(-0.635,2.925) 14(-1.905,2.925) 15(-3.175,2.925) 16(-4.445,2.925)
  silkscreen extent -5.4,-3.05 5,1.75
SOIC_16_NARROW [mm] "16 pin Narrow SOIC"
  rect 0.6x2.2 smd: 1(-4.445,-2.5) 2(-3.175,-2.5) 3(-1.905,-2.5) 4(-0.635,-2.5) 5(0.635,-2.5) 6(1.905,-2.5) 7(3.175,-2.5) 8(4.445,-2.5) 9(4.445,2.5) 10(3.175,2.5) 11(1.905,2.5) 12(0.635,2.5) 13(-0.635,2.5) 14(-1.905,2.5) 15(-3.175,2.5) 16(-4.445,2.5)
  silkscreen extent -5.42,-2.62 5,1
SOIC_20_WIDE [mm] "Small Outline; 20 Leads; Body Width 7.5 mm; Pitch 1.27 mm"
  rect 0.6x2.2 smd: 1(-5.715,-4.6) 2(-4.445,-4.6) 3(-3.175,-4.6) 4(-1.905,-4.6) 5(-0.635,-4.6) 6(0.635,-4.6) 7(1.905,-4.6) 8(3.175,-4.6) 9(4.445,-4.6) 10(5.715,-4.6) 11(5.715,4.6) 12(4.445,4.6) 13(3.175,4.6) 14(1.905,4.6) 15(0.635,4.6) 16(-0.635,4.6) 17(-1.905,4.6) 18(-3.175,4.6) 19(-4.445,4.6) 20(-5.715,4.6)
  silkscreen extent -6.69,-4.72 6.53,3.1
SOT23 [mm]
  rect 0.85x1 smd: 1(-0.95,-1.2) 2(0.95,-1.2) 3(0,1.2)
  silkscreen extent -2.05,-1.32 1.28,1.2
SWITCH_TL6120AF300QG [mm] "Switch, Tactile, SPST, NO"
  rect 1x3.1 smd: 1(2,4.5) 2(-2,4.5) 3(2,-4.5) 4(-2,-4.5)
  silkscreen extent -3.6,-3.6 3.6,3.6
TP_COMPACT [mil] "5005-5009 Compact Test Points"
  round 100 hole 63: 1(0,0)
  silkscreen extent -65,-65 65,65
TQ100 [mm]
  rect 1.6x0.3 smd: 1(-7.6,6) 2(-7.6,5.5) 3(-7.6,5) 4(-7.6,4.5) 5(-7.6,4) 6(-7.6,3.5) 7(-7.6,3) 8(-7.6,2.5) 9(-7.6,2) 10(-7.6,1.5) 11(-7.6,1) 12(-7.6,0.5) 13(-7.6,0) 14(-7.6,-0.5) 15(-7.6,-1) 16(-7.6,-1.5) 17(-7.6,-2) 18(-7.6,-2.5) 19(-7.6,-3) 20(-7.6,-3.5) 21(-7.6,-4) 22(-7.6,-4.5) 23(-7.6,-5) 24(-7.6,-5.5) 25(-7.6,-6) 51(7.6,-6) 52(7.6,-5.5) 53(7.6,-5) 54(7.6,-4.5) 55(7.6,-4) 56(7.6,-3.5) 57(7.6,-3) 58(7.6,-2.5) 59(7.6,-2) 60(7.6,-1.5) 61(7.6,-1) 62(7.6,-0.5) 63(7.6,0) 64(7.6,0.5) 65(7.6,1) 66(7.6,1.5) 67(7.6,2) 68(7.6,2.5) 69(7.6,3) 70(7.6,3.5) 71(7.6,4) 72(7.6,4.5) 73(7.6,5) 74(7.6,5.5) 75(7.6,6)
  rect 0.3x1.6 smd: 26(-6,-7.6) 27(-5.5,-7.6) 28(-5,-7.6) 29(-4.5,-7.6) 30(-4,-7.6) 31(-3.5,-7.6) 32(-3,-7.6) 33(-2.5,-7.6) 34(-2,-7.6) 35(-1.5,-7.6) 36(-1,-7.6) 37(-0.5,-7.6) 38(0,-7.6) 39(0.5,-7.6) 40(1,-7.6) 41(1.5,-7.6) 42(2,-7.6) 43(2.5,-7.6) 44(3,-7.6) 45(3.5,-7.6) 46(4,-7.6) 47(4.5,-7.6) 48(5,-7.6) 49(5.5,-7.6) 50(6,-7.6) 76(6,7.6) 77(5.5,7.6) 78(5,7.6) 79(4.5,7.6) 80(4,7.6) 81(3.5,7.6) 82(3,7.6) 83(2.5,7.6) 84(2,7.6) 85(1.5,7.6) 86(1,7.6) 87(0.5,7.6) 88(0,7.6) 89(-0.5,7.6) 90(-1,7.6) 91(-1.5,7.6) 92(-2,7.6) 93(-2.5,7.6) 94(-3,7.6) 95(-3.5,7.6) 96(-4,7.6) 97(-4.5,7.6) 98(-5,7.6) 99(-5.5,7.6) 100(-6,7.6)
  silkscreen extent -12.7,-12.7 12.7,12.7
ZJYS51R5-M4PA_INDCUTOR [mm] "Inductor, CM, 4 line"
  rect 1.6x1.6 smd: 1(-3.81,-4.15) 2(-1.27,-4.15) 3(1.27,-4.15) 4(3.81,-4.15) 5(3.81,4.15) 6(1.27,4.15) 7(-1.27,4.15) 8(-3.81,4.15)
  silkscreen extent -5.5,-4.32 5.5,3.05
